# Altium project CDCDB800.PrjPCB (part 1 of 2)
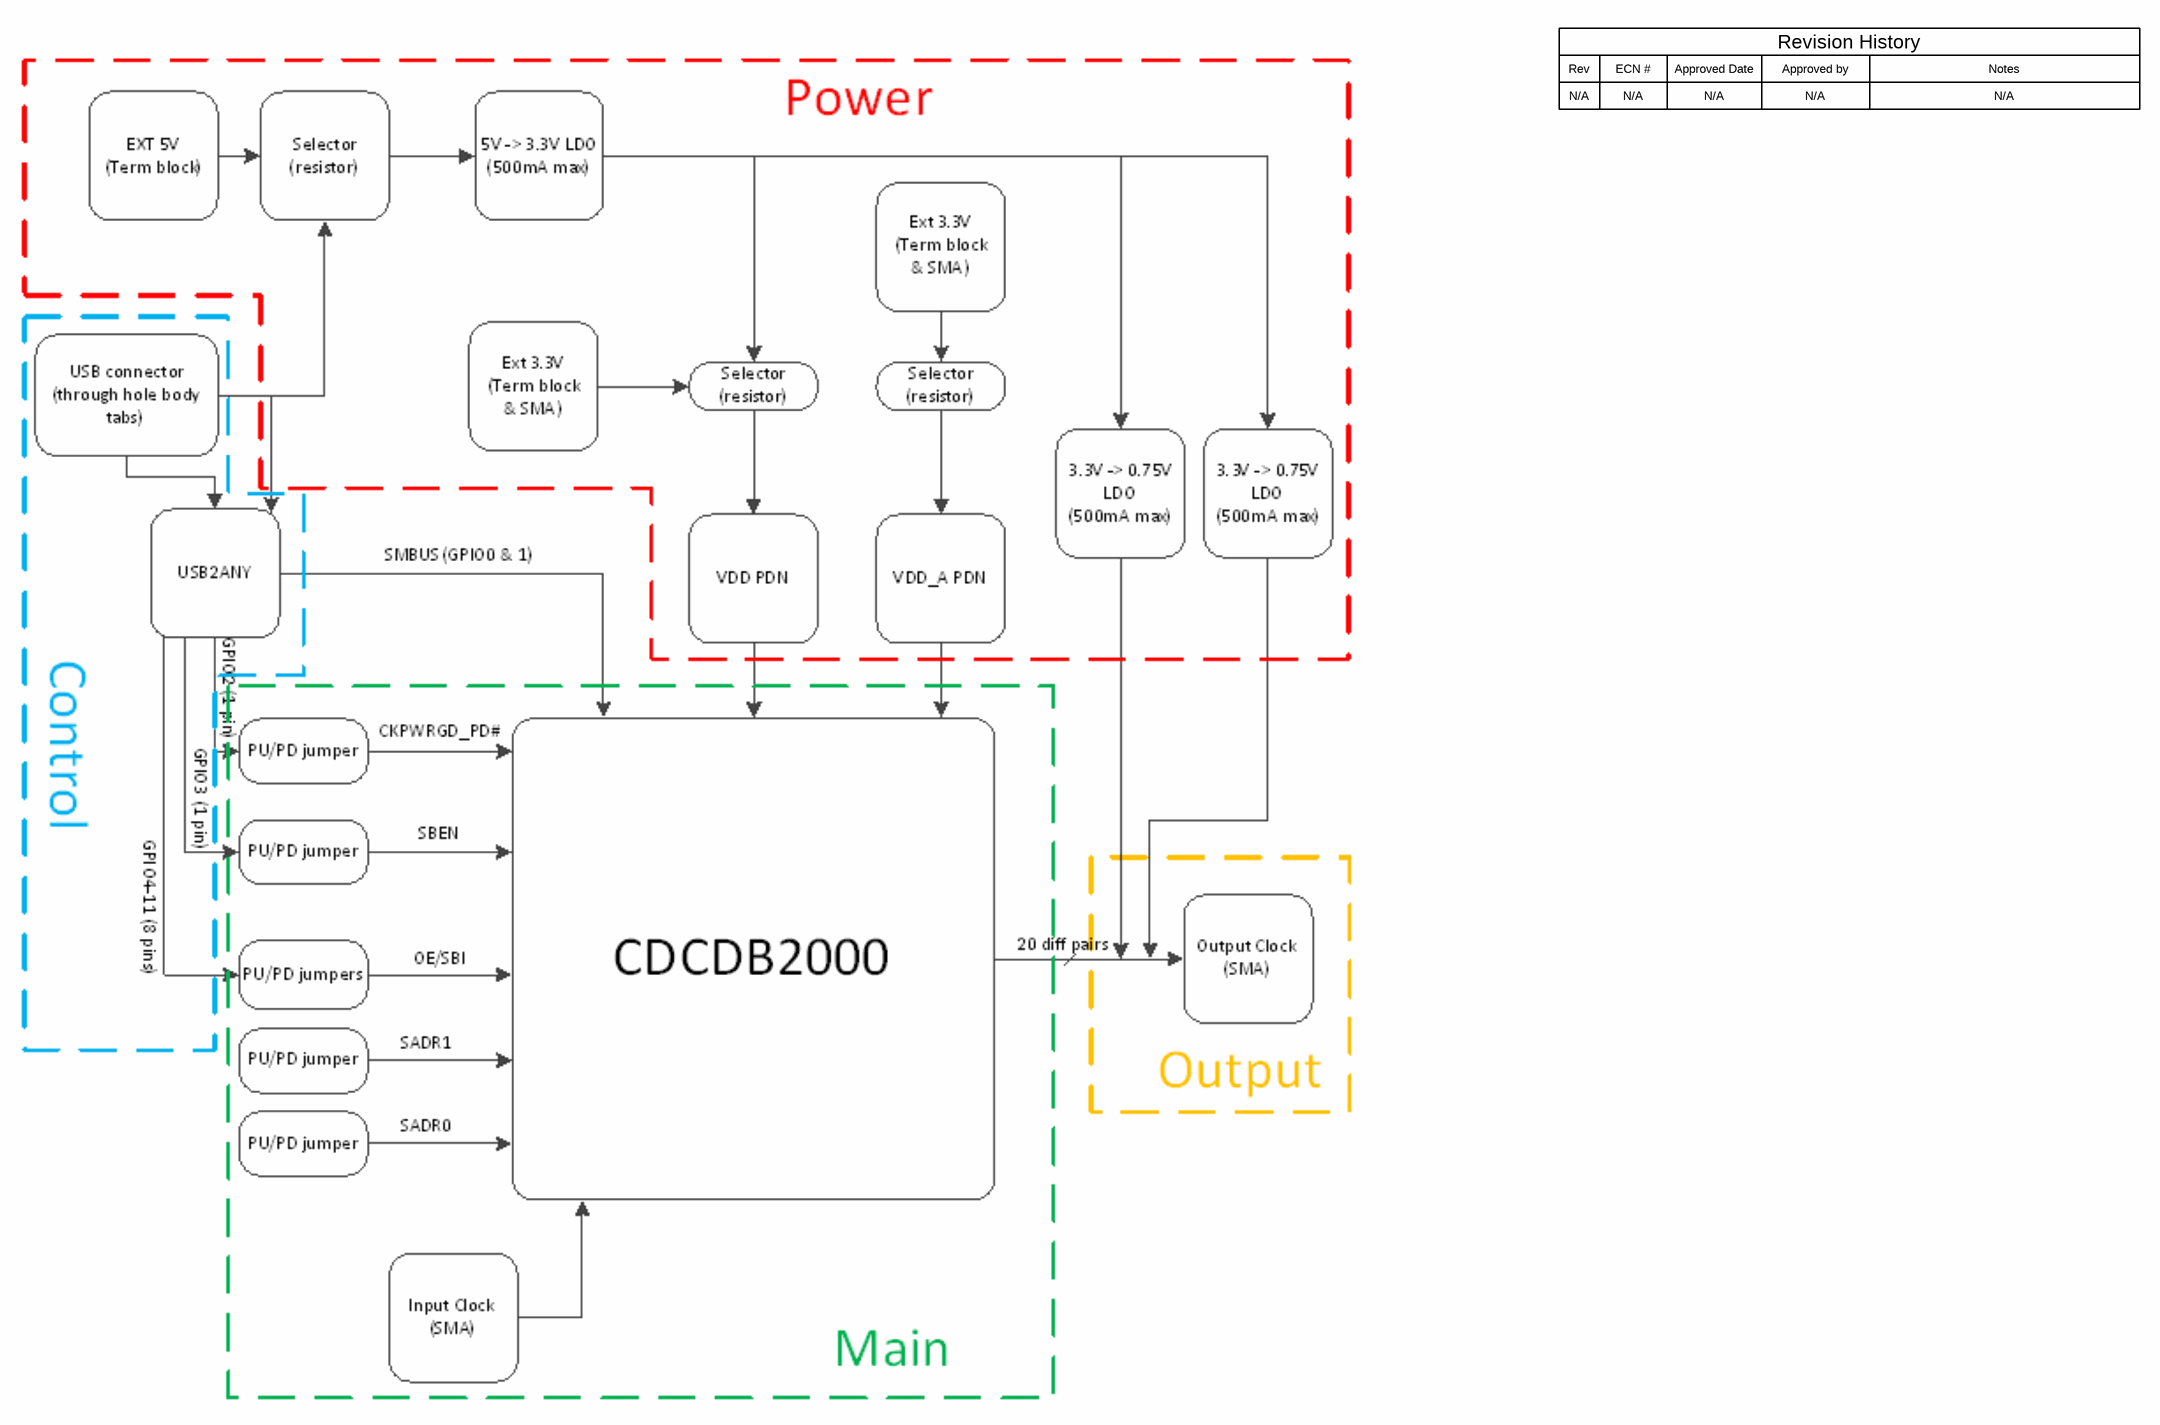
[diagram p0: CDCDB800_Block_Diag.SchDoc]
TID: N/A; TechSupport: http://www.ti.com/support; SCH_Rev: A; PRJ_Title: CDCDB800 EVM; PRJ_Number: CDCDB800; PRJ_Customer: Public Release; PCB_Rev: A; EVM_Orderable: CDCDB800 EVM; CopyrightYear: 2021
6 sheets, 245 parts. Net scope: flat (ports and power ports of the same name join across sheets).
Board file: CDCDB800.PcbDoc
Sheets:
  CDCDB800_Block_Diag.SchDoc
  CDCDB800_Control.SchDoc
  CDCDB800_Hardware.SchDoc
  CDCDB800_Main.SchDoc
  CDCDB800_Output.SchDoc
  CDCDB800_Power.SchDoc

## Sheet CDCDB800_Block_Diag.SchDoc: Block Diagram
size C; Date: Not shown in title block; ApprovedBy: Not shown in title block; CheckedBy: Not shown in title block; Author: Not shown in title block; CompanyName: Not shown in title block; DrawnBy: Robert Pulatie; Engineer: Not shown in title block; Organization: Not shown in title block; Address1: Not shown in title block; Address2: Not shown in title block; Address3: Not shown in title block; Address4: Not shown in title block; DocumentNumber: 1; Revision: Use project parameter SCH_Rev; SheetNumber: 1; SheetTotal: 6; PageSetup: Record=PageOptions¦CenterHorizontal=True¦CenterVertical=True¦PrintScale=1.00¦XCorrection=1.00¦YCorrection=1.00¦PrintKind=0¦BorderSize=5000000¦LeftOffset=0¦BottomOffset=0¦Orientation=2¦PaperLength=1000¦PaperWidth=1000¦Scale=100¦PaperSource=15¦PrintQuality=600¦MediaType=1¦DitherType=10¦PaperKind=Letter¦PrintScaleMode=1

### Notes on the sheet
- Rev
- N/A
- ECN #
- Approved Date
- Approved by
- Revision History
- Notes

## Sheet CDCDB800_Control.SchDoc: Control
size C; Date: Not shown in title block; ApprovedBy: Not shown in title block; CheckedBy: Not shown in title block; Author: Not shown in title block; CompanyName: Not shown in title block; DrawnBy: Robert Pulatie; Engineer: Not shown in title block; Organization: Not shown in title block; Address1: Not shown in title block; Address2: Not shown in title block; Address3: Not shown in title block; Address4: Not shown in title block; DocumentNumber: 5; Revision: Use project parameter SCH_Rev; SheetNumber: 5; SheetTotal: 6; PageSetup: Record=PageOptions¦CenterHorizontal=True¦CenterVertical=True¦PrintScale=1.00¦XCorrection=1.00¦YCorrection=1.00¦PrintKind=0¦BorderSize=5000000¦LeftOffset=0¦BottomOffset=0¦Orientation=2¦PaperLength=1000¦PaperWidth=1000¦Scale=100¦PaperSource=15¦PrintQuality=600¦MediaType=1¦DitherType=10¦PaperKind=Letter¦PrintScaleMode=1
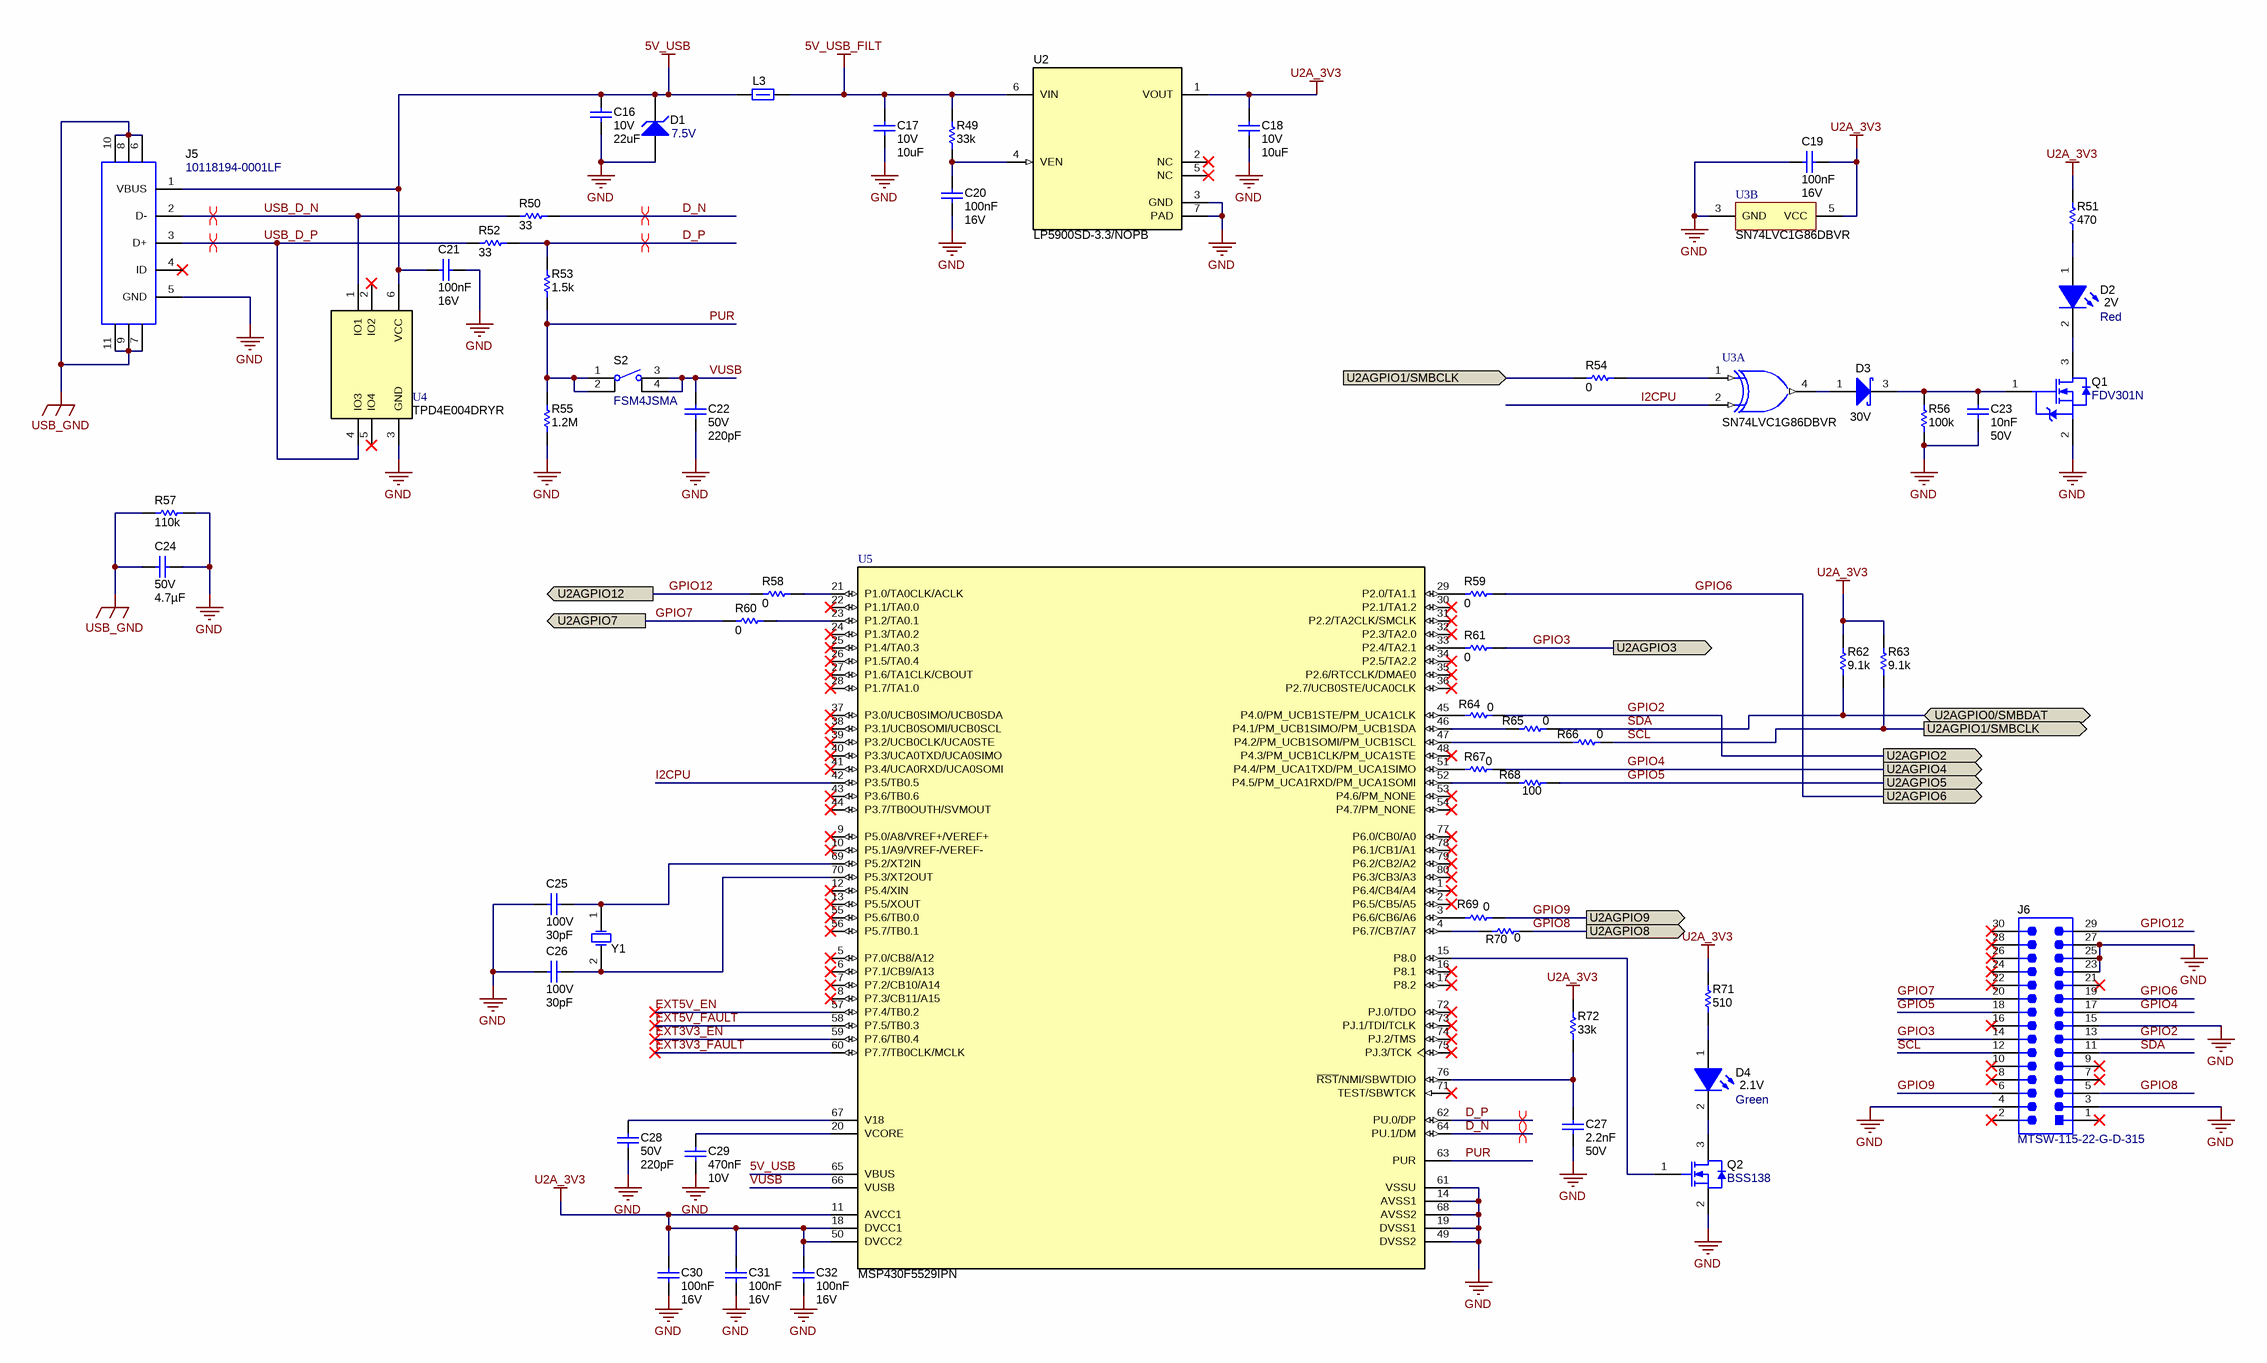
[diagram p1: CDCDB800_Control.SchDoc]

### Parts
C16  VDC_V: 10V  ValueDisplayed: 22uF  [0805_HV]  (hidden comment: LMK212BJ226MG-T)
C17  VDC_V: 10V  ValueDisplayed: 10uF  [0603]  (hidden comment: C1608X5R1A106M080AC)
C18  VDC_V: 10V  ValueDisplayed: 10uF  [0603]  (hidden comment: C1608X5R1A106M080AC)
C19  Cap_F: 100nF  VDC_V: 16V  [0603]  (hidden comment: C0603C104J4RACTU)
C20  Cap_F: 100nF  VDC_V: 16V  [0603]  (hidden comment: C0603C104J4RACTU)
C21  Cap_F: 100nF  VDC_V: 16V  [0603]  (hidden comment: C0603C104J4RACTU)
C22  VDC_V: 50V  ValueDisplayed: 220pF  [0603]  (hidden comment: 06035A221FAT2A)
C23  Cap_F: 10nF  VDC_V: 50V  [0603]  (hidden comment: C0603C103J5RACTU)
C24  VDC_V: 50V  ValueDisplayed: 4.7µF  [1206_190]  (hidden comment: C3216X7R1H475K160AE)
C25  VDC_V: 100V  ValueDisplayed: 30pF  [0603]  (hidden comment: GRM1885C2A300JA01D)
C26  VDC_V: 100V  ValueDisplayed: 30pF  [0603]  (hidden comment: GRM1885C2A300JA01D)
C27  Cap_F: 2.2nF  VDC_V: 50V  [0603]  (hidden comment: C0603C222K5RACTU)
C28  VDC_V: 50V  ValueDisplayed: 220pF  [0603]  (hidden comment: 06035A221FAT2A)
C29  Cap_F: 470nF  VDC_V: 10V  [0603]  (hidden comment: GRM188R71A474KA61D)
C30  Cap_F: 100nF  VDC_V: 16V  [0603]  (hidden comment: C0603C104J4RACTU)
C31  Cap_F: 100nF  VDC_V: 16V  [0603]  (hidden comment: C0603C104J4RACTU)
C32  Cap_F: 100nF  VDC_V: 16V  [0603]  (hidden comment: C0603C104J4RACTU)
D1  value 7.5V  [SMB]  (hidden comment: 1SMB5922BT3G)
D2  value Red  Value2: 2V  [LED_LTST-C170_Red]  (hidden comment: LTST-C170KRKT)
D3  value 30V  [SOT-23]  (hidden comment: BAT54-7-F)
D4  value Green  Value2: 2.1V  [LED_LTST-C190]  (hidden comment: LTST-C190GKT)
J5  10118194-0001LF  [FCI_10118194-0001LF]
J6  MTSW-115-22-G-D-315  [SAMTEC_MTSW-115-22-G-D-315]
L3  MPZ1608S600ATAH0  [0603]  (value not drawn)
Q1  FDV301N  [SOT-23]
Q2  BSS138  [SOT-23]
R49  ValueDisplayed: 33k  [0603]  (hidden comment: CRCW060333K0JNEA)
R50  ValueDisplayed: 33  [0402]  (hidden comment: CRCW040233R0JNED)
R51  ValueDisplayed: 470  [0603]  (hidden comment: CRCW0603470RJNEA)
R52  ValueDisplayed: 33  [0402]  (hidden comment: CRCW040233R0JNED)
R53  ValueDisplayed: 1.5k  [0402]  (hidden comment: CRCW04021K50JNED)
R54  ValueDisplayed: 0  [0603]  (hidden comment: CRCW06030000Z0EA)
R55  ValueDisplayed: 1.2M  [0603]  (hidden comment: CRCW06031M20JNEA)
R56  ValueDisplayed: 100k  [0603]  (hidden comment: CRCW0603100KJNEA)
R57  ValueDisplayed: 110k  [1206]  (hidden comment: RC1206FR-07110KL)
R58  ValueDisplayed: 0  [0603]  (hidden comment: CRCW06030000Z0EA)
R59  ValueDisplayed: 0  [0603]  (hidden comment: CRCW06030000Z0EA)
R60  ValueDisplayed: 0  [0603]  (hidden comment: CRCW06030000Z0EA)
R61  ValueDisplayed: 0  [0603]  (hidden comment: CRCW06030000Z0EA)
R62  ValueDisplayed: 9.1k  [0603]  (hidden comment: RC0603JR-079K1L)
R63  ValueDisplayed: 9.1k  [0603]  (hidden comment: RC0603JR-079K1L)
R64  ValueDisplayed: 0  [0603]  (hidden comment: CRCW06030000Z0EA)
R65  ValueDisplayed: 0  [0603]  (hidden comment: CRCW06030000Z0EA)
R66  ValueDisplayed: 0  [0603]  (hidden comment: CRCW06030000Z0EA)
R67  ValueDisplayed: 0  [0603]  (hidden comment: CRCW06030000Z0EA)
R68  ValueDisplayed: 100  [0603]  (hidden comment: CRCW0603100RJNEA)
R69  ValueDisplayed: 0  [0603]  (hidden comment: CRCW06030000Z0EA)
R70  ValueDisplayed: 0  [0603]  (hidden comment: CRCW06030000Z0EA)
R71  ValueDisplayed: 510  [0603]  (hidden comment: CRCW0603510RJNEA)
R72  ValueDisplayed: 33k  [0603]  (hidden comment: CRCW060333K0JNEA)
S2  FSM4JSMA  [SW_FSM4JSMA]
U2  LP5900SD-3.3/NOPB  [NGF0006A]
U3  SN74LVC1G86DBVR  [DBV0005A_N]  (parts A,B of 2)
U4  TPD4E004DRYR  [DRY0006A]
U5  MSP430F5529IPN  [PN0080A_N]
Y1  ECS-240-20-5PX-TR  [XTAL_CSM-7X]  (value not drawn)

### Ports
U2AGPIO0/SMBDAT (bidir), U2AGPIO1/SMBCLK (in), U2AGPIO1/SMBCLK (out), U2AGPIO2 (out), U2AGPIO3 (out), U2AGPIO4 (out), U2AGPIO5 (out), U2AGPIO6 (out), U2AGPIO7 (out), U2AGPIO8 (out), U2AGPIO9 (out), U2AGPIO12 (out)

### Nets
5V_USB: C16.1 C21.2 D1.1(K) J5.1(VBUS) L3.1 U4.6(VCC) U5.65(VBUS)
5V_USB_FILT: C17.1 L3.2 R49.2 U2.6(VIN)
GND: C16.2 C17.2 C18.2 C19.2 C20.2 C21.1 C22.2 C23.2 C24.1 C25.2 C26.2 C27.2 C28.2 C29.2 C30.2 C31.2 C32.2 D1.2(A) J5.5(GND) J6.3 J6.4 J6.15 J6.23 J6.25 J6.27 Q1.2(S) Q2.2(S) R55.1 R56.1 R57.2 U2.3(GND) U2.7(PAD) U3.3(GND) U4.3(GND) U5.14(AVSS1) U5.19(DVSS1) U5.49(DVSS2) U5.61(VSSU) U5.68(AVSS2)
U2A_3V3: C18.1 C19.1 C30.1 C31.1 C32.1 R51.2 R62.2 R63.2 R71.2 R72.2 U2.1(VOUT) U3.5(VCC) U5.11(AVCC1) U5.18(DVCC1) U5.50(DVCC2)
USB_GND: C24.2 J5.6 J5.7 J5.8 J5.9 J5.10 J5.11 R57.1
D_N: R50.2 U5.64(PU.1/DM)
D_P: R52.2 R53.2 U5.62(PU.0/DP)
EXT3V3_EN: U5.59(P7.6/TB0.4)
EXT3V3_FAULT: U5.60(P7.7/TB0CLK/MCLK)
EXT5V_EN: U5.57(P7.4/TB0.2)
EXT5V_FAULT: U5.58(P7.5/TB0.3)
GPIO2: J6.13 R64.2 ; port U2AGPIO2
GPIO3: J6.14 R61.2 ; port U2AGPIO3
GPIO4: J6.17 R67.2 ; port U2AGPIO4
GPIO5: J6.18 R68.2 ; port U2AGPIO5
GPIO6: J6.19 R59.2 ; port U2AGPIO6
GPIO7: J6.20 R60.1 ; port U2AGPIO7
GPIO8: J6.5 R70.2 ; port U2AGPIO8
GPIO9: J6.6 R69.2 ; port U2AGPIO9
GPIO12: J6.29 R58.1 ; port U2AGPIO12
I2CPU: U3.2(B) U5.42(P3.5/TB0.5)
PUR: R53.1 R55.2 S2.1 S2.2 U5.63(PUR)
SCL: J6.12 R54.1 R63.1 R66.2 ; port U2AGPIO1/SMBCLK
SDA: J6.11 R62.1 R65.2 ; port U2AGPIO0/SMBDAT
USB_D_N: J5.2(D-) R50.1 U4.1(IO1)
USB_D_P: J5.3(D+) R52.1 U4.4(IO3)
VUSB: C22.1 S2.3 S2.4 U5.66(VUSB)
NetC20_1: C20.1 R49.1 U2.4(VEN)
NetC23_1: C23.1 D3.3(K) Q1.1(G) R56.2
NetC25_1: C25.1 U5.69(P5.2/XT2IN) Y1.1(OSC1)
NetC26_1: C26.1 U5.70(P5.3/XT2OUT) Y1.2(OSC2)
NetC27_1: C27.1 R72.1 U5.76(~{RST}/NMI/SBWTDIO)
NetC28_1: C28.1 U5.67(V18)
NetC29_1: C29.1 U5.20(VCORE)
NetD2_1: D2.1(A) R51.1
NetD2_2: D2.2(K) Q1.3(D)
NetD3_1: D3.1(A) U3.4(Y)
NetD4_1: D4.1(A) R71.1
NetD4_2: D4.2(K) Q2.3(D)
NetQ2_1: Q2.1(G) U5.15(P8.0)
NetR54_2: R54.2 U3.1(A)
NetR58_2: R58.2 U5.21(P1.0/TA0CLK/ACLK)
NetR59_1: R59.1 U5.29(P2.0/TA1.1)
NetR60_2: R60.2 U5.23(P1.2/TA0.1)
NetR61_1: R61.1 U5.33(P2.4/TA2.1)
NetR64_1: R64.1 U5.45(P4.0/PM_UCB1STE/PM_UCA1CLK)
NetR65_1: R65.1 U5.46(P4.1/PM_UCB1SIMO/PM_UCB1SDA)
NetR66_1: R66.1 U5.47(P4.2/PM_UCB1SOMI/PM_UCB1SCL)
NetR67_1: R67.1 U5.51(P4.4/PM_UCA1TXD/PM_UCA1SIMO)
NetR68_1: R68.1 U5.52(P4.5/PM_UCA1RXD/PM_UCA1SOMI)
NetR69_1: R69.1 U5.3(P6.6/CB6/A6)
NetR70_1: R70.1 U5.4(P6.7/CB7/A7)

Not connected (* = marked no-connect by the designer): J5 4(ID)*; J6 1* 2* 7* 8* 9* 10* 16* 21* 22* 24* 26* 28* 30*; U2 2(NC)* 5(NC)*; U4 2(IO2)* 5(IO4)*; U5 1(P6.4/CB4/A4)* 2(P6.5/CB5/A5)* 5(P7.0/CB8/A12)* 6(P7.1/CB9/A13)* 7(P7.2/CB10/A14)* 8(P7.3/CB11/A15)* 9(P5.0/A8/VREF+/VEREF+)* 10(P5.1/A9/VREF-/VEREF-)* 12(P5.4/XIN)* 13(P5.5/XOUT)* 16(P8.1)* 17(P8.2)* 22(P1.1/TA0.0)* 24(P1.3/TA0.2)* 25(P1.4/TA0.3)* 26(P1.5/TA0.4)* 27(P1.6/TA1CLK/CBOUT)* 28(P1.7/TA1.0)* 30(P2.1/TA1.2)* 31(P2.2/TA2CLK/SMCLK)* 32(P2.3/TA2.0)* 34(P2.5/TA2.2)* 35(P2.6/RTCCLK/DMAE0)* 36(P2.7/UCB0STE/UCA0CLK)* 37(P3.0/UCB0SIMO/UCB0SDA)* 38(P3.1/UCB0SOMI/UCB0SCL)* 39(P3.2/UCB0CLK/UCA0STE)* 40(P3.3/UCA0TXD/UCA0SIMO)* 41(P3.4/UCA0RXD/UCA0SOMI)* 43(P3.6/TB0.6)* 44(P3.7/TB0OUTH/SVMOUT)* 48(P4.3/PM_UCB1CLK/PM_UCA1STE)* 53(P4.6/PM_NONE)* 54(P4.7/PM_NONE)* 55(P5.6/TB0.0)* 56(P5.7/TB0.1)* 71(TEST/SBWTCK)* 72(PJ.0/TDO)* 73(PJ.1/TDI/TCLK)* 74(PJ.2/TMS)* 75(PJ.3/TCK)* 77(P6.0/CB0/A0)* 78(P6.1/CB1/A1)* 79(P6.2/CB2/A2)* 80(P6.3/CB3/A3)*

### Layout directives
differential pair: D_N, D_P, USB_D_N, USB_D_P

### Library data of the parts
C16 = CMP-0008403-2: CAP, CERM, 22 uF, 10 V, +/- 20%, X5R, 0805; Manufacturer: Taiyo Yuden; TaMin_C: -55°C; Polarized: N; SizeAreaWB_mm2: 6.75; Value1: Unknown; U/M: EA; Value: 22uF; TaMax_C: 85°C; SizeZ_mm: 1.45; SizeX_mm: 2; SizeY_mm: 1.25; Cap_Case: 0805; SizeArea_mm2: 2.5; Cap_F: 22µF; AEC Category: Q200
C17 C18 = CMP-0007003-5: CAP, CERM, 10 uF, 10 V, +/- 20%, X5R, 0603; Manufacturer: TDK; TaMin_C: -55°C; ESR_ohm: 7.8m; Polarized: N; SizeAreaWB_mm2: 4.68; Value1: 0.0078 ohm; U/M: EA; Value: 10uF; TaMax_C: 85°C; SizeZ_mm: 1; SizeX_mm: 1.6; SizeY_mm: 0.8; SizeArea_mm2: 1.28; Cap_F: 10µF; IRMS_A: 1.85A; AEC Category: Q200
C19-C21 C30-C32 = CMP-0006857-4: CAP, CERM, 0.1 uF, 16 V, +/- 5%, X7R, 0603; Manufacturer: Kemet; TaMin_C: -55°C; Polarized: N; SizeAreaWB_mm2: 4.68; Value1: Unknown; U/M: EA; Value: 0.1uF; TaMax_C: 125°C; SizeZ_mm: 1; SizeX_mm: 1.6; SizeY_mm: 0.8; SizeArea_mm2: 1.28; AEC Category: Q200
C22 C28 = CMP-0006776-4: CAP, CERM, 220 pF, 50 V, +/- 1%, C0G/NP0, 0603; Manufacturer: AVX; TaMin_C: -55°C; ESR_ohm: 0.083; Polarized: N; SizeAreaWB_mm2: 4.68; Value1: 0.083 ohm; U/M: EA; Value: 220pF; TaMax_C: 125°C; SizeZ_mm: 1; SizeX_mm: 1.6; SizeY_mm: 0.8; SizeArea_mm2: 1.28; AEC Category: Q200
C23 = CMP-0006850-4: CAP, CERM, 0.01 uF, 50 V, +/- 5%, X7R, 0603; Manufacturer: Kemet; TaMin_C: -55°C; Polarized: N; SizeAreaWB_mm2: 4.68; Value1: Unknown; U/M: EA; Value: 0.01uF; TaMax_C: 125°C; SizeZ_mm: 1; SizeX_mm: 1.6; SizeY_mm: 0.8; SizeArea_mm2: 1.28; AEC Category: Q200
C24 = CMP-0082522-1: CAP, CERM, 4.7 µF, 50 V,+/- 10%, X7R, 1206; Manufacturer: TDK; SizeAreaWB_mm2: 10.92; SizeArea_mm2: 5.12; AEC Qualified: N; AEC Category: Q200; Value: 4.7uF; TaMax_C: 125°C; SizeZ_mm: 1.9; TaMin_C: -55°C; SizeY_mm: 1.6; U/M: EA; SizeX_mm: 3.2; Cap_Case: 1206
C25 C26 = CMP-0007261-4: CAP, CERM, 30 pF, 100 V, +/- 5%, C0G/NP0, 0603; Manufacturer: MuRata; TaMin_C: -55°C; Polarized: N; SizeAreaWB_mm2: 4.68; Value1: Unknown; U/M: EA; Value: 30pF; TaMax_C: 125°C; SizeZ_mm: 1; SizeX_mm: 1.6; SizeY_mm: 0.8; SizeArea_mm2: 1.28; AEC Category: Q200
C27 = CMP-0006898-4: CAP, CERM, 2200 pF, 50 V, +/- 10%, X7R, 0603; Manufacturer: Kemet; TaMin_C: -55°C; Polarized: N; SizeAreaWB_mm2: 4.68; Value1: Unknown; U/M: EA; Value: 2200pF; TaMax_C: 125°C; SizeZ_mm: 1; SizeX_mm: 1.6; SizeY_mm: 0.8; SizeArea_mm2: 1.28; AEC Category: Q200
C29 = CMP-0007373-4: CAP, CERM, 0.47 uF, 10 V, +/- 10%, X7R, 0603; Manufacturer: MuRata; TaMin_C: -55°C; Polarized: N; SizeAreaWB_mm2: 4.68; Value1: Unknown; U/M: EA; Value: 0.47uF; TaMax_C: 125°C; SizeZ_mm: 1; SizeX_mm: 1.6; SizeY_mm: 0.8; SizeArea_mm2: 1.28; AEC Category: Q200
D1 = CMP-0005670-3: Diode, Zener, 7.5 V, 550 mW, SMB; Manufacturer: ON Semiconductor; SizeArea_mm2: 21.336; SizeY_mm: 3.81; Value1: 0.55W; Power_W: 550mW; SizeZ_mm: 2.6; AEC Category: Q101; RJA_CperW: 226; SizeX_mm: 5.6; SizeAreaWB_mm2: 44.156
D2 = CMP-0002829-3: LED, Red, SMD; Manufacturer: Lite-On; SizeZ_mm: 1.2; Value1: W; SizeY_mm: 1.25; SizeArea_mm2: 2.5; SizeX_mm: 2; SizeAreaWB_mm2: 6.75; Io_A: 20mA; Type: AlInGaP
D3 = CMP-0028451-2: Diode, Schottky, 30 V, 0.2 A, SOT-23; Manufacturer: Diodes Inc.; SizeAreaWB_mm2: 14; SizeZ_mm: 1.1; Green_Lifecycle: Active; SizeY_mm: 3; Io_A: 200mA; SizeArea_mm2: 7.5; Green_REACh: Passed; Value1: 0.2A; Value2: 0.65V; TJmax_C: 125°C; Vf_V: 650mV; AEC Category: Q101; SizeX_mm: 2.5
D4 = CMP-0002827-3: LED, Green, SMD; Manufacturer: Lite-On; Power_TotalModule: 100mW; Io_A: 20mA; Value1: 0.1W
J5 = CMP-0074596-2: Receptacle, USB 2.0, Micro-USB Type B, R/A, SMT; Manufacturer: FCI; CNHeader: False; Current_A: 1.8A; Gender: Female; Voltage_V: 100V; Row_Count: 1; Pitch_mm: 0.65; ContactFinish: Gold; CT: True; Cert_UL: Y
J6 = CMP-0075468-1: Header, 100mil, 15x2, Gold, TH; Manufacturer: Samtec; Green_Lifecycle: Active; Green_REACh: Passed; CT: False; CNHeader: True
L3 = CMP-0003426-2: Ferrite Bead, 60 ohm @ 100 MHz, 3.5 A, 0603; Manufacturer: TDK; ZTyp@100MHz_Ohm: 60; SizeAreaWB_mm2: 4.68; DCR_ohm: 0.02; Value1: 0.02 ohm; Value: 60 ohm; Imax_A: 3.5A; SizeZ_mm: 1; SizeX_mm: 1.6; SizeY_mm: 0.8; SizeArea_mm2: 1.28
Q1 = CMP-0000281-1: MOSFET, N-CH, 25 V, 0.22 A, SOT-23; Alternate Manufacturer: None; Manufacturer: Fairchild Semiconductor; SizeZ_mm: 1.1; ChType: N; Value2: 0.49 nC; VdsMax_V: 25V; SizeX_mm: 2.5; SizeY_mm: 3; Vgs_V: 8V; Value: 25V; Rdson45_ohm: 4; SizeArea_mm2: 7.5; AEC Category: Q101; IdsMax_A: 220mA; SizeAreaWB_mm2: 14; U/M: EA; QgTyp_nC: 0.49
Q2 = CMP-0000755-1: MOSFET, N-CH, 50 V, 0.22 A, SOT-23; Alternate Manufacturer: None; Manufacturer: Fairchild Semiconductor; SizeZ_mm: 1.1; ChType: N; Value2: 1.7 nC; VdsMax_V: 50V; SizeX_mm: 2.5; SizeY_mm: 3; Vgs_V: 20V; Value: 50V; Rdson45_ohm: 6; SizeArea_mm2: 7.5; AEC Category: Q101; IdsMax_A: 220mA; SizeAreaWB_mm2: 14; U/M: EA; QgTyp_nC: 1.7
R49 R72 = CMP-0025786-4: RES, 33 k, 5%, 0.1 W, AEC-Q200 Grade 0, 0603; Manufacturer: Vishay-Dale; Power_W: 100mW; TempCo: 200 ppm/C; Value_Code: 33k0; Value: 33k; EIA_Code: E24; SizeX_mm: 1.6; SizeY_mm: 0.8; SizeZ_mm: 1; Value2: 0.1W; SizeArea_mm2: 1.28; AEC Qualified: Y; VDC_V: 75V; AEC Category: Q200; AEC Grade: 0
R50 R52 = CMP-0026908-3: RES, 33, 5%, 0.063 W, AEC-Q200 Grade 0, 0402; Manufacturer: Vishay-Dale; Power_W: 63mW; TempCo: 200 ppm/C; Value_Code: 33R0; Value: 33; EIA_Code: E24; SizeX_mm: 1; SizeY_mm: 0.5; SizeZ_mm: 0.6; Value2: 0.063W; AEC Qualified: Y; VDC_V: 50V; AEC Category: Q200; AEC Grade: 0
R51 = CMP-0025813-4: RES, 470, 5%, 0.1 W, AEC-Q200 Grade 0, 0603; Manufacturer: Vishay-Dale; Power_W: 100mW; TempCo: 200 ppm/C; Value_Code: 470R; Value: 470; EIA_Code: E24; SizeX_mm: 1.6; SizeY_mm: 0.8; SizeZ_mm: 1; Value2: 0.1W; SizeArea_mm2: 1.28; AEC Qualified: Y; VDC_V: 75V; AEC Category: Q200; AEC Grade: 0
R53 = CMP-0026856-5: RES, 1.5 k, 5%, 0.063 W, AEC-Q200 Grade 0, 0402; Manufacturer: Vishay-Dale; Power_W: 63mW; TempCo: 200 ppm/C; Value_Code: 1k50; Value: 1.5k; EIA_Code: E24; SizeX_mm: 1; SizeY_mm: 0.5; SizeZ_mm: 0.6; Value2: 0.063W; AEC Qualified: Y; VDC_V: 50V; AEC Category: Q200; AEC Grade: 0
R54 R58-R61 R64-R67 R69 R70 = CMP-0025697-4: RES, 0, 5%, 0.1 W, AEC-Q200 Grade 0, 0603; Manufacturer: Vishay-Dale; Power_W: 100mW; TempCo: 200 ppm/C; Value_Code: 0000; Value: 0; EIA_Code: E24; SizeX_mm: 1.6; SizeY_mm: 0.8; SizeZ_mm: 1; Value2: 0.1W; SizeArea_mm2: 1.28; AEC Qualified: Y; VDC_V: 75V; AEC Category: Q200
R55 = CMP-0025738-4: RES, 1.2 M, 5%, 0.1 W, AEC-Q200 Grade 0, 0603; Manufacturer: Vishay-Dale; Power_W: 100mW; TempCo: 200 ppm/C; Value_Code: 1M20; Value: 1.2Meg; EIA_Code: E24; SizeX_mm: 1.6; SizeY_mm: 0.8; SizeZ_mm: 1; Value2: 0.1W; SizeArea_mm2: 1.28; AEC Qualified: Y; VDC_V: 75V; AEC Category: Q200; AEC Grade: 0
R56 = CMP-0025698-4: RES, 100 k, 5%, 0.1 W, AEC-Q200 Grade 0, 0603; Manufacturer: Vishay-Dale; Power_W: 100mW; TempCo: 200 ppm/C; Value: 100k; EIA_Code: E24; SizeX_mm: 1.6; SizeY_mm: 0.8; SizeZ_mm: 1; Value2: 0.1W; SizeArea_mm2: 1.28; AEC Qualified: Y; VDC_V: 75V; AEC Category: Q200; AEC Grade: 0
R57 = CMP-0017852-2: RES, 110 k, 1%, 0.25 W, 1206; Manufacturer: Yageo America; Power_W: 250mW; TempCo: 100 ppm/C; U/M: EA; Value: 110k; EIA_Code: E96; SizeX_mm: 3.2; SizeY_mm: 1.6; SizeZ_mm: 1.35; Value2: 0.25W; SizeArea_mm2: 5.12; VDC_V: 200V; AEC Category: Q200
R62 R63 = CMP-0025944-5: RES, 9.1 k, 5%, 0.1 W, 0603; Manufacturer: Yageo; Power_W: 100mW; TempCo: 100 ppm/C; Value_Code: 9k10; Value: 9.1k; EIA_Code: E24; SizeX_mm: 1.6; SizeY_mm: 0.8; SizeZ_mm: 1; Value2: 0.1W; SizeArea_mm2: 1.28; AEC Qualified: N; VDC_V: 75V; AEC Category: Q200; SizeAreaWB_mm2: 4.68
R68 = CMP-0025700-4: RES, 100, 5%, 0.1 W, AEC-Q200 Grade 0, 0603; Manufacturer: Vishay-Dale; Power_W: 100mW; TempCo: 200 ppm/C; Value_Code: 100R; Value: 100; EIA_Code: E24; SizeX_mm: 1.6; SizeY_mm: 0.8; SizeZ_mm: 1; Value2: 0.1W; SizeArea_mm2: 1.28; AEC Qualified: Y; VDC_V: 75V; AEC Category: Q200; AEC Grade: 0
R71 = CMP-0025823-4: RES, 510, 5%, 0.1 W, AEC-Q200 Grade 0, 0603; Manufacturer: Vishay-Dale; Power_W: 100mW; TempCo: 200 ppm/C; Value_Code: 510R; Value: 510; EIA_Code: E24; SizeX_mm: 1.6; SizeY_mm: 0.8; SizeZ_mm: 1; Value2: 0.1W; SizeArea_mm2: 1.28; AEC Qualified: Y; VDC_V: 75V; AEC Category: Q200; AEC Grade: 0
S2 = CMP-0002134-3: Switch, Tactile, SPST-NO, 0.05A, 12V, SMT; Manufacturer: TE Connectivity; CurrentRating_mA: 50A; PositionCount: 1; SwitchFunction: Off-Mom
U2 = CMP-0066010-1: 150-mA Ultra-Low Noise LDO for RF and Analog Circuits Requires No Bypass Capacitor, NGF0006A (WSON-6); Alternate Manufacturer: Texas Instruments; Green_Lifecycle: Active; SizeAreaWB_mm2: 11.2; Green_REACh: Passed; U/M: EA; SizeZ_mm: 0.8; SizeX_mm: 2.5; SizeY_mm: 2.2; SizeArea_mm2: 5.5; CompType: IC
U3 = CMP-0052046-2: Single 2-Input Exclusive-OR Gate, DBV0005A (SOT-23-5); Manufacturer: Texas Instruments; Schmitt Trigger: No; Output Type: CMOS; Bits(#): 1; Rating: Catalog; VCC(Max)(V): 5.5; Input Type: CMOS/TTL; F @ Nom Voltage(Max)(Mhz): 150; Voltage(Nom)(V): 1.8,2.5,3.3,5; VCC(Min)(V): 1.65; Output Drive (IOL/IOH)(Max)(mA): 32/-32; ICC @ Nom Voltage(Max)(mA): 0.01; Logic: True; Gate Type: XOR; tpd @ Nom Voltage(Max)(ns): 9.9,5.5,5,4; AEC Category: Q200; AEC Qualified: N; CompType: IC; SizeAreaWB_mm2: 14.82; SizeArea_mm2: 8.12; SizeX_mm: 2.8; SizeY_mm: 2.9; SizeZ_mm: 1.45
U4 = CMP-0043115-3: 4-Channel ESD Protection Array for High-Speed Data Interfaces, DRY0006A (USON-6); Manufacturer: Texas Instruments; IO Leakage Current(nA): 1; USB High Speed: TRUE; IO Capacitance(Typ)(pF): 1.6; Eco-Plan: Green (RoHS & no Sb/Br); IEC 61000-4-2 Contact(+/- kV): 8; Breakdown Voltage(Min)(V): 6; IEC 61000-4-2 Air-Gap(+/- kV): 12; AEC Category: Q200; AEC Qualified: N; CompType: IC; SizeAreaWB_mm2: 4.9; SizeArea_mm2: 1.45; SizeX_mm: 1.0; SizeZ_mm: 0.6; Rating: Catalog
U5 = CMP-0038965-1: 25 MHz Mixed Signal Microcontroller with 128 KB Flash, 8192 B SRAM and 63 GPIOs, -40 to 85 degC, 80-pin QFP (PN), Green (RoHS & no Sb/Br); Manufacturer: Texas Instruments; Real-Time Clock: Yes; Multiplier: 32x32; Frequency(MHz): 25; USCI_A (UART/LIN/IrDA/SPI): 2; SubFamily: 5 Series; Timers - 16-bit: 4; ADC Channels: 16; GPIO: 63; SRAM(B): 8192; DMA: 3; ADC: 12-bit SAR; Flash(KB): 128; USB: 1
Y1 = CMP-0004572-3: Crystal, 24.000 MHz, 20pF, SMD; Manufacturer: ECS Inc.; TaMin_C: -10°C; Frequency Stability: +/-50ppm; Frequency_Fixed: 24MHz; TaMax_C: 70°C

## Sheet CDCDB800_Hardware.SchDoc: Hardware
size C; Date: Not shown in title block; ApprovedBy: Not shown in title block; CheckedBy: Not shown in title block; Author: Not shown in title block; CompanyName: Not shown in title block; DrawnBy: Robert Pulatie; Engineer: Not shown in title block; Organization: Not shown in title block; Address1: Not shown in title block; Address2: Not shown in title block; Address3: Not shown in title block; Address4: Not shown in title block; DocumentNumber: 6; Revision: Use project parameter SCH_Rev; SheetNumber: 6; SheetTotal: 6; PageSetup: Record=PageOptions¦CenterHorizontal=True¦CenterVertical=True¦PrintScale=1.00¦XCorrection=1.00¦YCorrection=1.00¦PrintKind=0¦BorderSize=5000000¦LeftOffset=0¦BottomOffset=0¦Orientation=2¦PaperLength=1000¦PaperWidth=1000¦Scale=100¦PaperSource=15¦PrintQuality=600¦MediaType=1¦DitherType=10¦PaperKind=Letter¦PrintScaleMode=1
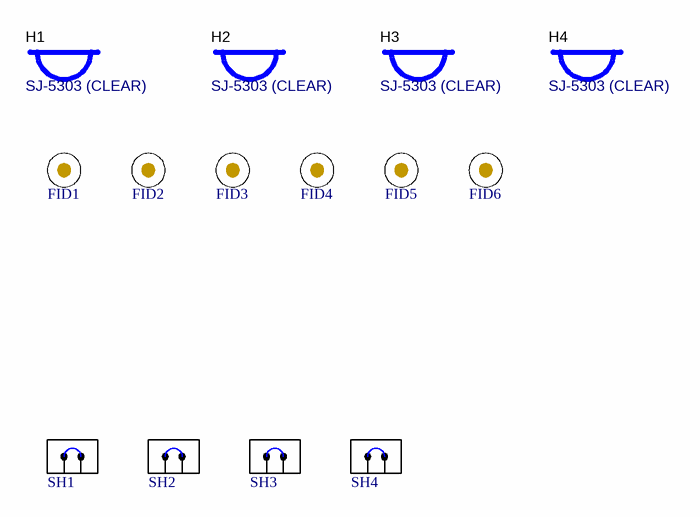
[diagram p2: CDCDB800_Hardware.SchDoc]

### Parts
FID1  Fiducial  [Fiducial10-20]  (value not drawn)
FID2  Fiducial  [Fiducial10-20]  (value not drawn)
FID3  Fiducial  [Fiducial10-20]  (value not drawn)
FID4  Fiducial  [Fiducial10-20]  (value not drawn)
FID5  Fiducial  [Fiducial10-20]  (value not drawn)
FID6  Fiducial  [Fiducial10-20]  (value not drawn)
H1  SJ-5303 (CLEAR)  [Bumpon_SJ5003Transparent]
H2  SJ-5303 (CLEAR)  [Bumpon_SJ5003Transparent]
H3  SJ-5303 (CLEAR)  [Bumpon_SJ5003Transparent]
H4  SJ-5303 (CLEAR)  [Bumpon_SJ5003Transparent]
SH1  SNT-100-BK-G  [SNT-100-BK-G]  (value not drawn)
SH2  SNT-100-BK-G  [SNT-100-BK-G]  (value not drawn)
SH3  SNT-100-BK-G  [SNT-100-BK-G]  (value not drawn)
SH4  SNT-100-BK-G  [SNT-100-BK-G]  (value not drawn)

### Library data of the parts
FID1-FID6 = CMP-0077181-1: Fiducial mark.  There is nothing to buy or mount.
H1-H4 = CMP-0003620-1: Bumpon, Hemisphere, 0.44 X 0.20, Clear; Manufacturer: 3M
SH1-SH4 = CMP-0003623-3: Shunt, 100mil, Gold plated, Black; Alternate PartNumber: 969102-0000-DA; Manufacturer: Samtec; Alternate Manufacturer: 3M; Value: 1x2; Note: You can "mate" this to a header by matching the designator.  i.e. use SH-J3 for header J3

## Sheet CDCDB800_Main.SchDoc: Main
size C; Date: Not shown in title block; ApprovedBy: Not shown in title block; CheckedBy: Not shown in title block; Author: Not shown in title block; CompanyName: Not shown in title block; DrawnBy: Robert Pulatie; Engineer: Not shown in title block; Organization: Not shown in title block; Address1: Not shown in title block; Address2: Not shown in title block; Address3: Not shown in title block; Address4: Not shown in title block; DocumentNumber: 3; Revision: Use project parameter SCH_Rev; SheetNumber: 3; SheetTotal: 6; PageSetup: Record=PageOptions¦CenterHorizontal=True¦CenterVertical=True¦PrintScale=1.00¦XCorrection=1.00¦YCorrection=1.00¦PrintKind=0¦BorderSize=5000000¦LeftOffset=0¦BottomOffset=0¦Orientation=2¦PaperLength=1000¦PaperWidth=1000¦Scale=100¦PaperSource=15¦PrintQuality=600¦MediaType=1¦DitherType=10¦PaperKind=Letter¦PrintScaleMode=1
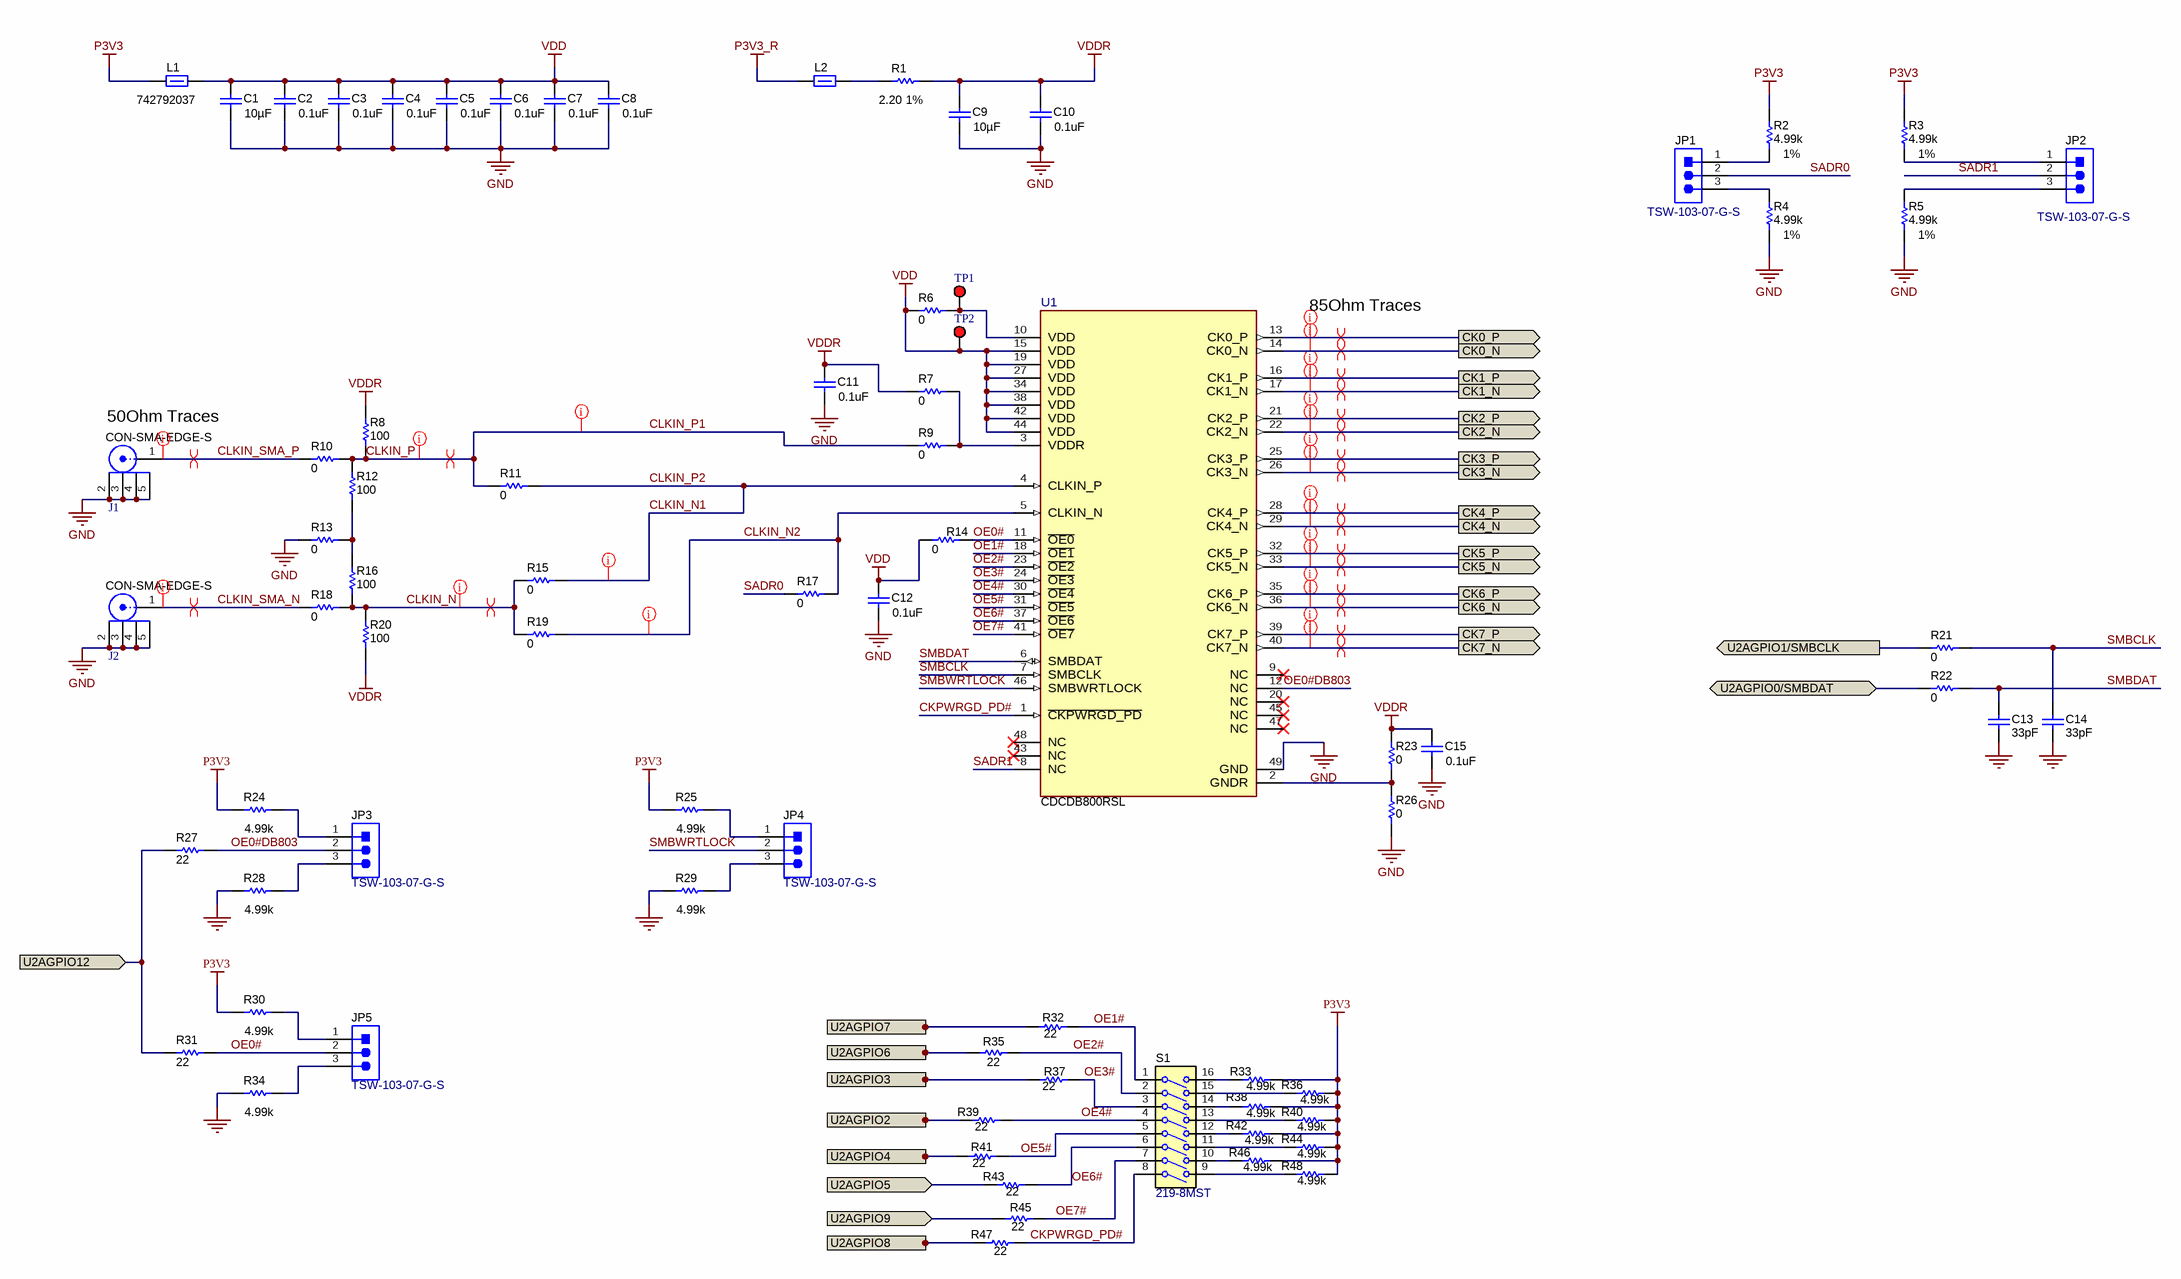
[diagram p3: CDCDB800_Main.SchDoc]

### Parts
C1  ValueDisplayed: 10µF  [0603]  (hidden comment: GRM188C81C106MA73D)
C2  ValueDisplayed: 0.1uF  [0402]  (hidden comment: GRM155R71A104KA01D)
C3  ValueDisplayed: 0.1uF  [0402]  (hidden comment: GRM155R71A104KA01D)
C4  ValueDisplayed: 0.1uF  [0402]  (hidden comment: GRM155R71A104KA01D)
C5  ValueDisplayed: 0.1uF  [0402]  (hidden comment: GRM155R71A104KA01D)
C6  ValueDisplayed: 0.1uF  [0402]  (hidden comment: GRM155R71A104KA01D)
C7  ValueDisplayed: 0.1uF  [0402]  (hidden comment: GRM155R71A104KA01D)
C8  ValueDisplayed: 0.1uF  [0402]  (hidden comment: GRM155R71A104KA01D)
C9  ValueDisplayed: 10µF  [0603]  (hidden comment: GRM188C81C106MA73D)
C10  ValueDisplayed: 0.1uF  [0402]  (hidden comment: GRM155R71A104KA01D)
C11  ValueDisplayed: 0.1uF  [0402]  (hidden comment: GRM155R71A104KA01D)
C12  ValueDisplayed: 0.1uF  [0402]  (hidden comment: GRM155R71A104KA01D)
C13  ValueDisplayed: 33pF  [0603S]  (hidden comment: 06031A330JAT2A)
C14  ValueDisplayed: 33pF  [0603S]  (hidden comment: 06031A330JAT2A)
C15  ValueDisplayed: 0.1uF  [0402]  (hidden comment: GRM155R71A104KA01D)
J1  CON-SMA-EDGE-S  [FP-SMA-EDGE-S-CUSTOM]
J2  CON-SMA-EDGE-S  [FP-SMA-EDGE-S-CUSTOM]
JP1  TSW-103-07-G-S  [TSW-103-07-G-S]
JP2  TSW-103-07-G-S  [TSW-103-07-G-S]
JP3  TSW-103-07-G-S  [TSW-103-07-G-S]
JP4  TSW-103-07-G-S  [TSW-103-07-G-S]
JP5  TSW-103-07-G-S  [TSW-103-07-G-S]
L1  742792037  [0805_HV]
L2  742792037  [0805_HV]  (value not drawn)
R1  Tolerance_%: 1%  ValueDisplayed: 2.20  [0603]  (hidden comment: ERJ-3RQF2R2V)
R2  Value1: 1%  ValueDisplayed: 4.99k  [0402]  (hidden comment: RC0402FR-074K99L)
R3  Value1: 1%  ValueDisplayed: 4.99k  [0402]  (hidden comment: RC0402FR-074K99L)
R4  Value1: 1%  ValueDisplayed: 4.99k  [0402]  (hidden comment: RC0402FR-074K99L)
R5  Value1: 1%  ValueDisplayed: 4.99k  [0402]  (hidden comment: RC0402FR-074K99L)
R6  ValueDisplayed: 0  [0603]  (hidden comment: MCT06030Z0000ZP500)
R7  ValueDisplayed: 0  [0603]  (hidden comment: RC0603JR-070RL)
R8  ValueDisplayed: 100  [0603]  (hidden comment: CRCW0603100RFKEA)
R9  ValueDisplayed: 0  [0603]  (hidden comment: RC0603JR-070RL)
R10  ValueDisplayed: 0  [0603]  (hidden comment: RC0603JR-070RL)
R11  ValueDisplayed: 0  [0603]  (hidden comment: RC0603JR-070RL)
R12  ValueDisplayed: 100  [0603]  (hidden comment: CRCW0603100RFKEA)
R13  ValueDisplayed: 0  [0603]  (hidden comment: RC0603JR-070RL)
R14  ValueDisplayed: 0  [0603]  (hidden comment: MCT06030Z0000ZP500)
R15  ValueDisplayed: 0  [0603]  (hidden comment: RC0603JR-070RL)
R16  ValueDisplayed: 100  [0603]  (hidden comment: CRCW0603100RFKEA)
R17  ValueDisplayed: 0  [0603]  (hidden comment: RC0603JR-070RL)
R18  ValueDisplayed: 0  [0603]  (hidden comment: RC0603JR-070RL)
R19  ValueDisplayed: 0  [0603]  (hidden comment: RC0603JR-070RL)
R20  ValueDisplayed: 100  [0603]  (hidden comment: CRCW0603100RFKEA)
R21  ValueDisplayed: 0  [0603L]  (hidden comment: CRCW06030000Z0EA)
R22  ValueDisplayed: 0  [0603L]  (hidden comment: CRCW06030000Z0EA)
R23  ValueDisplayed: 0  [0603]  (hidden comment: MCT06030Z0000ZP500)
R24  ValueDisplayed: 4.99k  [0402]  (hidden comment: RC0402FR-074K99L)
R25  ValueDisplayed: 4.99k  [0402]  (hidden comment: RC0402FR-074K99L)
R26  ValueDisplayed: 0  [0603]  (hidden comment: MCT06030Z0000ZP500)
R27  ValueDisplayed: 22  [0603]  (hidden comment: CRCW060322R0JNEA)
R28  ValueDisplayed: 4.99k  [0402]  (hidden comment: RC0402FR-074K99L)
R29  ValueDisplayed: 4.99k  [0402]  (hidden comment: RC0402FR-074K99L)
R30  ValueDisplayed: 4.99k  [0402]  (hidden comment: RC0402FR-074K99L)
R31  ValueDisplayed: 22  [0603]  (hidden comment: CRCW060322R0JNEA)
R32  ValueDisplayed: 22  [0603]  (hidden comment: CRCW060322R0JNEA)
R33  ValueDisplayed: 4.99k  [0402]  (hidden comment: RC0402FR-074K99L)
R34  ValueDisplayed: 4.99k  [0402]  (hidden comment: RC0402FR-074K99L)
R35  ValueDisplayed: 22  [0603]  (hidden comment: CRCW060322R0JNEA)
R36  ValueDisplayed: 4.99k  [0402]  (hidden comment: RC0402FR-074K99L)
R37  ValueDisplayed: 22  [0603]  (hidden comment: CRCW060322R0JNEA)
R38  ValueDisplayed: 4.99k  [0402]  (hidden comment: RC0402FR-074K99L)
R39  ValueDisplayed: 22  [0603]  (hidden comment: CRCW060322R0JNEA)
R40  ValueDisplayed: 4.99k  [0402]  (hidden comment: RC0402FR-074K99L)
R41  ValueDisplayed: 22  [0603]  (hidden comment: CRCW060322R0JNEA)
R42  ValueDisplayed: 4.99k  [0402]  (hidden comment: RC0402FR-074K99L)
R43  ValueDisplayed: 22  [0603]  (hidden comment: CRCW060322R0JNEA)
R44  ValueDisplayed: 4.99k  [0402]  (hidden comment: RC0402FR-074K99L)
R45  ValueDisplayed: 22  [0603]  (hidden comment: CRCW060322R0JNEA)
R46  ValueDisplayed: 4.99k  [0402]  (hidden comment: RC0402FR-074K99L)
R47  ValueDisplayed: 22  [0603]  (hidden comment: CRCW060322R0JNEA)
R48  ValueDisplayed: 4.99k  [0402]  (hidden comment: RC0402FR-074K99L)
S1  219-8MST  [SW_219-8MST]
TP1  5010  [Keystone5010]  (value not drawn)
TP2  5010  [Keystone5010]  (value not drawn)
U1  CDCDB800RSL  [RSL0048B-MFG]

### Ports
CK0_N (out), CK0_P (out), CK1_N (out), CK1_P (out), CK2_N (out), CK2_P (out), CK3_N (out), CK3_P (out), CK4_N (out), CK4_P (out), CK5_N (out), CK5_P (out), CK6_N (out), CK6_P (out), CK7_N (out), CK7_P (out), U2AGPIO0/SMBDAT (bidir), U2AGPIO1/SMBCLK (out), U2AGPIO2 (in), U2AGPIO3 (in), U2AGPIO4 (in), U2AGPIO5 (in), U2AGPIO6 (in), U2AGPIO7 (in), U2AGPIO8 (in), U2AGPIO9 (in), U2AGPIO12 (in)

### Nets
GND: C1.2 C2.2 C3.2 C4.2 C5.2 C6.2 C7.2 C8.2 C9.2 C10.2 C11.2 C12.2 C13.2 C14.2 C15.2 J1.2 J1.3 J1.4 J1.5 J2.2 J2.3 J2.4 J2.5 R4.1 R5.1 R13.1 R26.1 R28.2 R29.2 R34.2 U1.49(GND)
P3V3: L1.1 R2.2 R3.2 R24.2 R25.2 R30.2 R33.1 R36.1 R38.1 R40.1 R42.1 R44.2 R46.2 R48.2
P3V3_R: L2.1
VDD: C1.1 C2.1 C3.1 C4.1 C5.1 C6.1 C7.1 C8.1 C12.1 L1.2 R6.1 R14.2 TP2.1 U1.15(VDD) U1.19(VDD) U1.27(VDD) U1.34(VDD) U1.38(VDD) U1.42(VDD) U1.44(VDD)
VDDR: C9.1 C10.1 C11.1 C15.1 R1.2 R7.1 R8.1 R20.2 R23.2
CK0_N: U1.14(CK0_N) ; port CK0_N
CK0_P: U1.13(CK0_P) ; port CK0_P
CK1_N: U1.17(CK1_N) ; port CK1_N
CK1_P: U1.16(CK1_P) ; port CK1_P
CK2_N: U1.22(CK2_N) ; port CK2_N
CK2_P: U1.21(CK2_P) ; port CK2_P
CK3_N: U1.26(CK3_N) ; port CK3_N
CK3_P: U1.25(CK3_P) ; port CK3_P
CK4_N: U1.29(CK4_N) ; port CK4_N
CK4_P: U1.28(CK4_P) ; port CK4_P
CK5_N: U1.33(CK5_N) ; port CK5_N
CK5_P: U1.32(CK5_P) ; port CK5_P
CK6_N: U1.36(CK6_N) ; port CK6_N
CK6_P: U1.35(CK6_P) ; port CK6_P
CK7_N: U1.40(CK7_N) ; port CK7_N
CK7_P: U1.39(CK7_P) ; port CK7_P
CKPWRGD_PD#: R47.2 S1.8 U1.1(~{CKPWRGD_PD})
CLKIN_N: R15.1 R16.2 R18.2 R19.1 R20.1
CLKIN_N1: R11.2 R15.2 U1.4(CLKIN_P)  [also labelled CLKIN_P2]
CLKIN_N2: R17.2 R19.2 U1.5(CLKIN_N)
CLKIN_P: R8.2 R9.1 R10.2 R11.1 R12.1  [also labelled CLKIN_P1]
CLKIN_SMA_N: J2.1 R18.1
CLKIN_SMA_P: J1.1 R10.1
GPIO2: R39.1 ; port U2AGPIO2
GPIO3: R37.1 ; port U2AGPIO3
GPIO4: R41.1 ; port U2AGPIO4
GPIO5: R43.1 ; port U2AGPIO5
GPIO6: R35.1 ; port U2AGPIO6
GPIO7: R32.1 ; port U2AGPIO7
GPIO8: R47.1 ; port U2AGPIO8
GPIO9: R45.1 ; port U2AGPIO9
GPIO12: R27.1 R31.1 ; port U2AGPIO12
OE0#: JP5.2 R14.1 R31.2 U1.11(~{OE0})
OE0#DB803: JP3.2 R27.2 U1.12(NC)
OE1#: R32.2 S1.1 U1.18(~{OE1})
OE2#: R35.2 S1.2 U1.23(~{OE2})
OE3#: R37.2 S1.3 U1.24(~{OE3})
OE4#: R39.2 S1.4 U1.30(~{OE4})
OE5#: R41.2 S1.5 U1.31(~{OE5})
OE6#: R43.2 S1.6 U1.37(~{OE6})
OE7#: R45.2 S1.7 U1.41(~{OE7})
SADR0: JP1.2 R17.1
SADR1: JP2.2 U1.8(NC)
SCL: R21.1 ; port U2AGPIO1/SMBCLK
SDA: R22.1 ; port U2AGPIO0/SMBDAT
SMBCLK: C14.1 R21.2 U1.7(SMBCLK)
SMBDAT: C13.1 R22.2 U1.6(SMBDAT)
SMBWRTLOCK: JP4.2 U1.46(SMBWRTLOCK)
NetJP1_1: JP1.1 R2.1
NetJP1_3: JP1.3 R4.2
NetJP2_1: JP2.1 R3.1
NetJP2_3: JP2.3 R5.2
NetJP3_1: JP3.1 R24.1
NetJP3_3: JP3.3 R28.1
NetJP4_1: JP4.1 R25.1
NetJP4_3: JP4.3 R29.1
NetJP5_1: JP5.1 R30.1
NetJP5_3: JP5.3 R34.1
NetL2_2: L2.2 R1.1
NetR6_2: R6.2 TP1.1 U1.10(VDD)
NetR7_2: R7.2 R9.2 U1.3(VDDR)
NetR12_2: R12.2 R13.2 R16.1
NetR23_1: R23.1 R26.2 U1.2(GNDR)
NetR33_2: R33.2 S1.16(1A)
NetR36_2: R36.2 S1.15(2A)
NetR38_2: R38.2 S1.14(3A)
NetR40_2: R40.2 S1.13(4A)
NetR42_2: R42.2 S1.12(5A)
NetR44_1: R44.1 S1.11(6A)
NetR46_1: R46.1 S1.10(7A)
NetR48_1: R48.1 S1.9(8A)

Not connected (* = marked no-connect by the designer): U1 9(NC)* 20(NC)* 43(NC)* 45(NC)* 47(NC)* 48(NC)*

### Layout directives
differential pair: CK0_N, CK0_P, CK1_N, CK1_P, CK2_N, CK2_P, CK3_N, CK3_P, CK4_N, CK4_P, CK5_N, CK5_P, CK6_N, CK6_P, CK7_N, CK7_P, CLKIN_N, CLKIN_P, CLKIN_SMA_N, CLKIN_SMA_P
net class 85ohms: CK0_N, CK0_P, CK1_N, CK1_P, CK2_N, CK2_P, CK3_N, CK3_P, CK4_N, CK4_P, CK5_N, CK5_P, CK6_N, CK6_P, CK7_N, CK7_P
net class 50ohms: CLKIN_N, CLKIN_N1, CLKIN_N2, CLKIN_P, CLKIN_SMA_N, CLKIN_SMA_P

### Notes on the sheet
- (near U1) 85Ohm Traces
- (near J1) 50Ohm Traces

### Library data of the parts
C1 C9 = CMP-0086062-1: CAP, CERM, 10 µF, 16 V,+/- 20%, X6S, 0603; Manufacturer: MuRata; U/M: EA; AEC Category: Q200; VDC_V: 16V; SizeX_mm: 1.6; SizeY_mm: 0.8; SizeZ_mm: 1; Value: 10uF; SizeArea_mm2: 1.28; TaMin_C: -55°C; Polarized: N; SizeAreaWB_mm2: 4.68; TaMax_C: 105°C
C2-C8 C10-C12 C15 = CMP-0006629-2: CAP, CERM, 0.1 uF, 10 V, +/- 10%, X7R, 0402; Manufacturer: MuRata; TaMin_C: -55°C; Polarized: N; SizeAreaWB_mm2: 3; Value1: Unknown; U/M: EA; Value: 0.1uF; TaMax_C: 125°C; SizeZ_mm: 0.6; SizeX_mm: 1; SizeY_mm: 0.5; Value2: 10V; Cap_F: 100nF; AEC Category: Q200
C13 C14 = CMP-0006722-4: CAP, CERM, 33 pF, 100 V, +/- 5%, C0G/NP0, 0603; Manufacturer: AVX; Polarized: N; Value: 33pF; U/M: EA; ESR_ohm: 0.209; Value1: 0.209 ohm; VDC_V: 100V; TaMin_C: -55°C; TaMax_C: 125°C; Cap_Case: 0603; AEC Category: Q200; SizeArea_mm2: 1.28; SizeAreaWB_mm2: 4.68; SizeX_mm: 1.6; SizeY_mm: 0.8; SizeZ_mm: 1
J1 J2 = CMP-0088000-4: CONN SMA JACK STR EDGE MNT; Manufacturer: RF Solutions Ltd.; ContactFinish: Gold; Shrouded: true
JP1-JP5 = CMP-0075407-2: Header, 100mil, 3x1, Gold, TH; Manufacturer: Samtec; Cert_CSA: Y; Cert_CULUS: N; Current_A: 6.3A; Gender: Male; Green_Lifecycle: Active; Green_REACh: Passed; Pitch_mm: 2.54; Row_Count: 1; Voltage_V: 550V
L1 L2 = CMP-0003081-1: Ferrite Bead, 330 ohm @ 100 MHz, 2 A, 0805; Manufacturer: Wurth Elektronik; Ztyp@1GHz_Ohm: 170.834; ZTyp@100MHz_Ohm: 330; SizeAreaWB_mm2: 6.75; DCR_ohm: 0.08; Value1: 0.08 ohm; Value: 330 ohm; Imax_A: 2A; SizeZ_mm: 1.45; SizeX_mm: 2; SizeY_mm: 1.25; SizeArea_mm2: 2.5
R1 = CMP-0022711-2: RES, 2.20, 1%, 0.1 W, 0603; Manufacturer: Panasonic; Power_W: 100mW; TempCo: 200 ppm/C; Value_Code: 2R20; U/M: EA; Value: 2.20; Res_ohm: 2.2; SizeX_mm: 1.6; SizeY_mm: 0.8; SizeZ_mm: 1; Value2: 0.1W; SizeArea_mm2: 1.28; AEC Category: Q200
R2-R5 R24 R25 R28-R30 R33 R34 R36 R38 R40 R42 R44 R46 R48 = CMP-0026740-1: RES, 4.99 k, 1%, 0.063 W, 0402; Manufacturer: Yageo America; Power_W: 63mW; TempCo: 100 ppm/C; Value_Code: 4k99; U/M: EA; Value: 4.99k; EIA_Code: E96; SizeX_mm: 1; SizeY_mm: 0.5; SizeZ_mm: 0.6; Value2: 0.063W; AEC Qualified: N; VDC_V: 50V; AEC Category: Q200
R6 R14 R23 R26 = CMP-0025884-3: RES, 0, 5%, 0.125 W, 0603; Manufacturer: Vishay/Beyschlag; Power_W: 125mW; TempCo: ppm/C; Value_Code: 0000; U/M: EA; Value: 0; EIA_Code: E24; SizeX_mm: 1.6; SizeY_mm: 0.8; SizeZ_mm: 1; Value2: 0.125W; SizeArea_mm2: 1.28; AEC Qualified: N; AEC Category: Q200
R7 R9-R11 R13 R15 R17-R19 = CMP-0025885-5: RES, 0, 5%, 0.1 W, 0603; Manufacturer: Yageo; Power_W: 100mW; TempCo: 200 ppm/C; Value_Code: 0000; Value: 0; EIA_Code: E24; SizeX_mm: 1.6; SizeZ_mm: 1; Value2: 0.1W; SizeArea_mm2: 1.28; AEC Qualified: N; VDC_V: 75V; AEC Category: Q200; SizeY_mm: 0.8; SizeAreaWB_mm2: 4.68
R8 R12 R16 R20 = CMP-0021991-4: RES, 100, 1%, 0.1 W, AEC-Q200 Grade 0, 0603; Manufacturer: Vishay-Dale; Power_W: 100mW; TempCo: 100 ppm/C; Value_Code: 100R; Value: 100; EIA_Code: E96; SizeX_mm: 1.6; SizeY_mm: 0.8; SizeZ_mm: 1; Value2: 0.1W; SizeArea_mm2: 1.28; AEC Qualified: Y; VDC_V: 75V; AEC Category: Q200; AEC Grade: 0
R21 R22 = CMP-0025697-4: RES, 0, 5%, 0.1 W, AEC-Q200 Grade 0, 0603; Manufacturer: Vishay-Dale; Value: 0; Value_Code: 0000; Power_W: 100mW; Value2: 0.1W; VDC_V: 75V; TempCo: 200 ppm/C; EIA_Code: E24; AEC Category: Q200; AEC Qualified: Y; SizeArea_mm2: 1.28; SizeX_mm: 1.6; SizeY_mm: 0.8; SizeZ_mm: 1
R27 R31 R32 R35 R37 R39 R41 R43 R45 R47 = CMP-0025758-4: RES, 22, 5%, 0.1 W, AEC-Q200 Grade 0, 0603; Manufacturer: Vishay-Dale; Power_W: 100mW; TempCo: 200 ppm/C; Value_Code: 22R0; Value: 22; EIA_Code: E24; SizeX_mm: 1.6; SizeY_mm: 0.8; SizeZ_mm: 1; Value2: 0.1W; SizeArea_mm2: 1.28; AEC Qualified: Y; VDC_V: 75V; AEC Category: Q200; AEC Grade: 0
S1 = CMP-0002131-3: Switch, Slide, SPST 8 poles, SMT; Manufacturer: CTS Electrocomponents; VDC_V: 20V; SwitchFunction: Off-On; PositionCount: 8; CurrentRating_mA: 100A
TP1 TP2 = CMP-0055147-1: Test Point, Multipurpose, Red, TH; Manufacturer: Keystone; CNHeader: FALSE; Green_Lifecycle: Active; Green_REACh: Passed; ContactFinish: Silver; CT: TRUE
U1 = CMP-0091223-1: 8-output LP-HCSL clock buffer capable of distributing the reference clocks for PCIe Gen 1-5, QPI, UPI, SAS, and SATA interfaces; Manufacturer: Texas Instruments; Standoff Height: 0mm; Number Of Elements: 1; SizeZ_mm: 1mm; Min Supply Voltage: 2.97V; Logic Function: Non-Inverting; AEC Qualified: No; Number Of Outputs: 8; Nominal Supply Current: 5-63mA; Max Supply Voltage: 3.63V

## Sheet CDCDB800_Output.SchDoc: Output
size C; Date: Not shown in title block; ApprovedBy: Not shown in title block; CheckedBy: Not shown in title block; Author: Not shown in title block; CompanyName: Not shown in title block; DrawnBy: Robert Pulatie; Engineer: Not shown in title block; Organization: Not shown in title block; Address1: Not shown in title block; Address2: Not shown in title block; Address3: Not shown in title block; Address4: Not shown in title block; DocumentNumber: 4; Revision: Use project parameter SCH_Rev; SheetNumber: 4; SheetTotal: 6; PageSetup: Record=PageOptions¦CenterHorizontal=True¦CenterVertical=True¦PrintScale=1.00¦XCorrection=1.00¦YCorrection=1.00¦PrintKind=0¦BorderSize=5000000¦LeftOffset=0¦BottomOffset=0¦Orientation=2¦PaperLength=1000¦PaperWidth=1000¦Scale=100¦PaperSource=15¦PrintQuality=600¦MediaType=1¦DitherType=10¦PaperKind=Letter¦PrintScaleMode=1
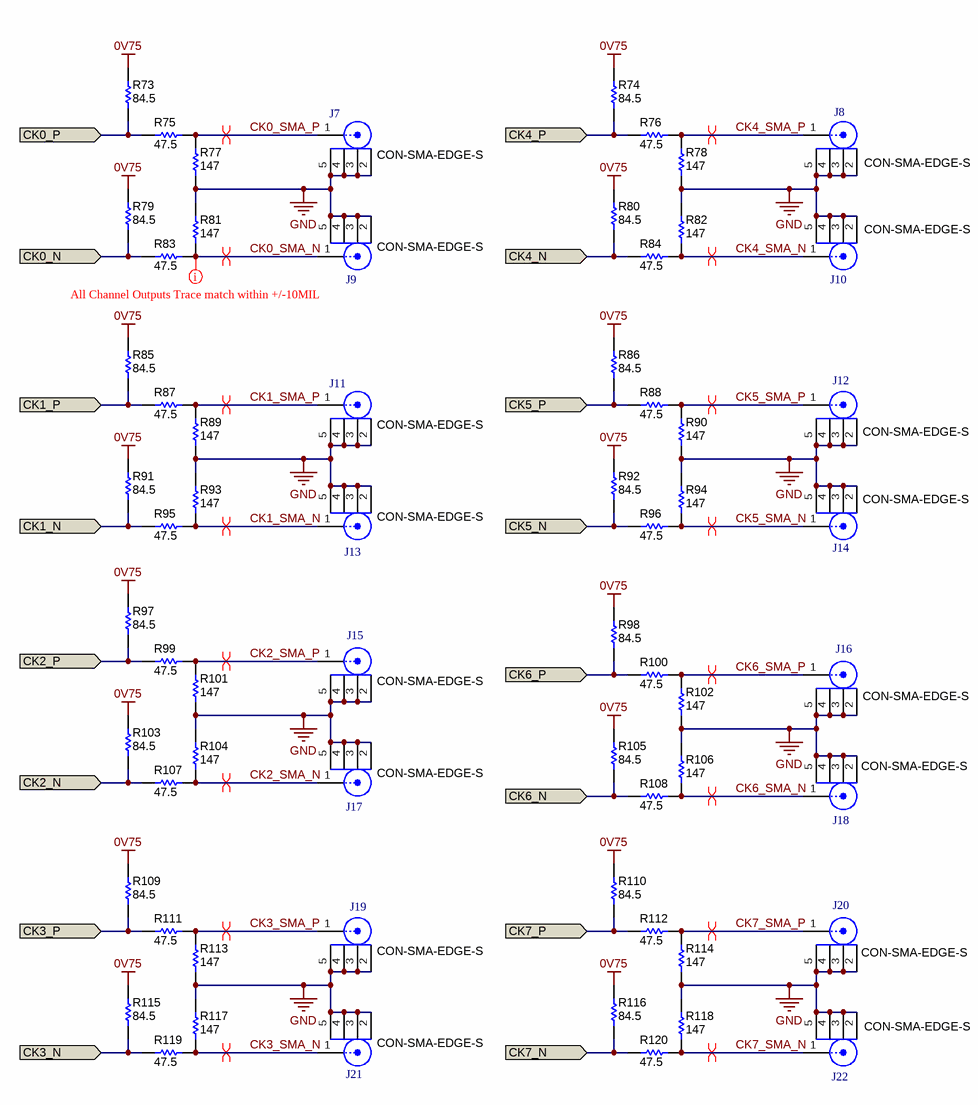
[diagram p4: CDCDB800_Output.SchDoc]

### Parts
J7  CON-SMA-EDGE-S  [FP-SMA-EDGE-S-CUSTOM]
J8  CON-SMA-EDGE-S  [FP-SMA-EDGE-S-CUSTOM]
J9  CON-SMA-EDGE-S  [FP-SMA-EDGE-S-CUSTOM]
J10  CON-SMA-EDGE-S  [FP-SMA-EDGE-S-CUSTOM]
J11  CON-SMA-EDGE-S  [FP-SMA-EDGE-S-CUSTOM]
J12  CON-SMA-EDGE-S  [FP-SMA-EDGE-S-CUSTOM]
J13  CON-SMA-EDGE-S  [FP-SMA-EDGE-S-CUSTOM]
J14  CON-SMA-EDGE-S  [FP-SMA-EDGE-S-CUSTOM]
J15  CON-SMA-EDGE-S  [FP-SMA-EDGE-S-CUSTOM]
J16  CON-SMA-EDGE-S  [FP-SMA-EDGE-S-CUSTOM]
J17  CON-SMA-EDGE-S  [FP-SMA-EDGE-S-CUSTOM]
J18  CON-SMA-EDGE-S  [FP-SMA-EDGE-S-CUSTOM]
J19  CON-SMA-EDGE-S  [FP-SMA-EDGE-S-CUSTOM]
J20  CON-SMA-EDGE-S  [FP-SMA-EDGE-S-CUSTOM]
J21  CON-SMA-EDGE-S  [FP-SMA-EDGE-S-CUSTOM]
J22  CON-SMA-EDGE-S  [FP-SMA-EDGE-S-CUSTOM]
R73  ValueDisplayed: 84.5  [0201]  (hidden comment: RC0201FR-0784R5L)
R74  ValueDisplayed: 84.5  [0201]  (hidden comment: RC0201FR-0784R5L)
R75  ValueDisplayed: 47.5  [0201]  (hidden comment: RC0201FR-0747R5L)
R76  ValueDisplayed: 47.5  [0201]  (hidden comment: RC0201FR-0747R5L)
R77  ValueDisplayed: 147  [0201]  (hidden comment: RC0201FR-07147RL)
R78  ValueDisplayed: 147  [0201]  (hidden comment: RC0201FR-07147RL)
R79  ValueDisplayed: 84.5  [0201]  (hidden comment: RC0201FR-0784R5L)
R80  ValueDisplayed: 84.5  [0201]  (hidden comment: RC0201FR-0784R5L)
R81  ValueDisplayed: 147  [0201]  (hidden comment: RC0201FR-07147RL)
R82  ValueDisplayed: 147  [0201]  (hidden comment: RC0201FR-07147RL)
R83  ValueDisplayed: 47.5  [0201]  (hidden comment: RC0201FR-0747R5L)
R84  ValueDisplayed: 47.5  [0201]  (hidden comment: RC0201FR-0747R5L)
R85  ValueDisplayed: 84.5  [0201]  (hidden comment: RC0201FR-0784R5L)
R86  ValueDisplayed: 84.5  [0201]  (hidden comment: RC0201FR-0784R5L)
R87  ValueDisplayed: 47.5  [0201]  (hidden comment: RC0201FR-0747R5L)
R88  ValueDisplayed: 47.5  [0201]  (hidden comment: RC0201FR-0747R5L)
R89  ValueDisplayed: 147  [0201]  (hidden comment: RC0201FR-07147RL)
R90  ValueDisplayed: 147  [0201]  (hidden comment: RC0201FR-07147RL)
R91  ValueDisplayed: 84.5  [0201]  (hidden comment: RC0201FR-0784R5L)
R92  ValueDisplayed: 84.5  [0201]  (hidden comment: RC0201FR-0784R5L)
R93  ValueDisplayed: 147  [0201]  (hidden comment: RC0201FR-07147RL)
R94  ValueDisplayed: 147  [0201]  (hidden comment: RC0201FR-07147RL)
R95  ValueDisplayed: 47.5  [0201]  (hidden comment: RC0201FR-0747R5L)
R96  ValueDisplayed: 47.5  [0201]  (hidden comment: RC0201FR-0747R5L)
R97  ValueDisplayed: 84.5  [0201]  (hidden comment: RC0201FR-0784R5L)
R98  ValueDisplayed: 84.5  [0201]  (hidden comment: RC0201FR-0784R5L)
R99  ValueDisplayed: 47.5  [0201]  (hidden comment: RC0201FR-0747R5L)
R100  ValueDisplayed: 47.5  [0201]  (hidden comment: RC0201FR-0747R5L)
R101  ValueDisplayed: 147  [0201]  (hidden comment: RC0201FR-07147RL)
R102  ValueDisplayed: 147  [0201]  (hidden comment: RC0201FR-07147RL)
R103  ValueDisplayed: 84.5  [0201]  (hidden comment: RC0201FR-0784R5L)
R104  ValueDisplayed: 147  [0201]  (hidden comment: RC0201FR-07147RL)
R105  ValueDisplayed: 84.5  [0201]  (hidden comment: RC0201FR-0784R5L)
R106  ValueDisplayed: 147  [0201]  (hidden comment: RC0201FR-07147RL)
R107  ValueDisplayed: 47.5  [0201]  (hidden comment: RC0201FR-0747R5L)
R108  ValueDisplayed: 47.5  [0201]  (hidden comment: RC0201FR-0747R5L)
R109  ValueDisplayed: 84.5  [0201]  (hidden comment: RC0201FR-0784R5L)
R110  ValueDisplayed: 84.5  [0201]  (hidden comment: RC0201FR-0784R5L)
R111  ValueDisplayed: 47.5  [0201]  (hidden comment: RC0201FR-0747R5L)
R112  ValueDisplayed: 47.5  [0201]  (hidden comment: RC0201FR-0747R5L)
R113  ValueDisplayed: 147  [0201]  (hidden comment: RC0201FR-07147RL)
R114  ValueDisplayed: 147  [0201]  (hidden comment: RC0201FR-07147RL)
R115  ValueDisplayed: 84.5  [0201]  (hidden comment: RC0201FR-0784R5L)
R116  ValueDisplayed: 84.5  [0201]  (hidden comment: RC0201FR-0784R5L)
R117  ValueDisplayed: 147  [0201]  (hidden comment: RC0201FR-07147RL)
R118  ValueDisplayed: 147  [0201]  (hidden comment: RC0201FR-07147RL)
R119  ValueDisplayed: 47.5  [0201]  (hidden comment: RC0201FR-0747R5L)
R120  ValueDisplayed: 47.5  [0201]  (hidden comment: RC0201FR-0747R5L)

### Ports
CK0_N (in), CK0_P (in), CK1_N (in), CK1_P (in), CK2_N (in), CK2_P (in), CK3_N (in), CK3_P (in), CK4_N (in), CK4_P (in), CK5_N (in), CK5_P (in), CK6_N (in), CK6_P (in), CK7_N (in), CK7_P (in)

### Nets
0V75: R73.2 R74.2 R79.2 R80.2 R85.2 R86.2 R91.2 R92.2 R97.2 R98.2 R103.2 R105.2 R109.2 R110.2 R115.2 R116.2
GND: J7.2 J7.3 J7.4 J7.5 J8.2 J8.3 J8.4 J8.5 J9.2 J9.3 J9.4 J9.5 J10.2 J10.3 J10.4 J10.5 J11.2 J11.3 J11.4 J11.5 J12.2 J12.3 J12.4 J12.5 J13.2 J13.3 J13.4 J13.5 J14.2 J14.3 J14.4 J14.5 J15.2 J15.3 J15.4 J15.5 J16.2 J16.3 J16.4 J16.5 J17.2 J17.3 J17.4 J17.5 J18.2 J18.3 J18.4 J18.5 J19.2 J19.3 J19.4 J19.5 J20.2 J20.3 J20.4 J20.5 J21.2 J21.3 J21.4 J21.5 J22.2 J22.3 J22.4 J22.5 R77.1 R78.1 R81.2 R82.2 R89.1 R90.1 R93.2 R94.2 R101.1 R102.1 R104.2 R106.2 R113.1 R114.1 R117.2 R118.2
CK0_N: R79.1 R83.1 ; port CK0_N
CK0_P: R73.1 R75.1 ; port CK0_P
CK0_SMA_N: J9.1 R81.1 R83.2
CK0_SMA_P: J7.1 R75.2 R77.2
CK1_N: R91.1 R95.1 ; port CK1_N
CK1_P: R85.1 R87.1 ; port CK1_P
CK1_SMA_N: J13.1 R93.1 R95.2
CK1_SMA_P: J11.1 R87.2 R89.2
CK2_N: R103.1 R107.1 ; port CK2_N
CK2_P: R97.1 R99.1 ; port CK2_P
CK2_SMA_N: J17.1 R104.1 R107.2
CK2_SMA_P: J15.1 R99.2 R101.2
CK3_N: R115.1 R119.1 ; port CK3_N
CK3_P: R109.1 R111.1 ; port CK3_P
CK3_SMA_N: J21.1 R117.1 R119.2
CK3_SMA_P: J19.1 R111.2 R113.2
CK4_N: R80.1 R84.1 ; port CK4_N
CK4_P: R74.1 R76.1 ; port CK4_P
CK4_SMA_N: J10.1 R82.1 R84.2
CK4_SMA_P: J8.1 R76.2 R78.2
CK5_N: R92.1 R96.1 ; port CK5_N
CK5_P: R86.1 R88.1 ; port CK5_P
CK5_SMA_N: J14.1 R94.1 R96.2
CK5_SMA_P: J12.1 R88.2 R90.2
CK6_N: R105.1 R108.1 ; port CK6_N
CK6_P: R98.1 R100.1 ; port CK6_P
CK6_SMA_N: J18.1 R106.1 R108.2
CK6_SMA_P: J16.1 R100.2 R102.2
CK7_N: R116.1 R120.1 ; port CK7_N
CK7_P: R110.1 R112.1 ; port CK7_P
CK7_SMA_N: J22.1 R118.1 R120.2
CK7_SMA_P: J20.1 R112.2 R114.2

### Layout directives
differential pair: CK0_SMA_N, CK0_SMA_P, CK1_SMA_N, CK1_SMA_P, CK2_SMA_N, CK2_SMA_P, CK3_SMA_N, CK3_SMA_P, CK4_SMA_N, CK4_SMA_P, CK5_SMA_N, CK5_SMA_P, CK6_SMA_N, CK6_SMA_P, CK7_SMA_N, CK7_SMA_P
mark named All Channel Outputs Trace match within +/-10MIL: CK0_SMA_N

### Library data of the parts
J7-J22 = CMP-0088000-4: as J1 on sheet CDCDB800_Main
R73 R79 R85 R86 R91 R92 R97 R98 R103 R105 R109 R110 R115 R116 = CMP-0027898-1: RES, 84.5, 1%, 0.05 W, 0201; Manufacturer: Yageo America; Power_W: 50mW; TempCo: 200 ppm/C; Value_Code: 84R5; U/M: EA; Value: 84.5; EIA_Code: E96; SizeX_mm: 0.6; SizeY_mm: 0.3; SizeZ_mm: 0.26; Value2: 0.05W; SizeArea_mm2: 0.18; AEC Qualified: N; VDC_V: 25V; AEC Category: Q200
R74 R80 = CMP-0027898-1: RES, 84.5, 1%, 0.05 W, 0201; Manufacturer: Yageo America; Power_W: 50mW; TempCo: 200 ppm/C; Value_Code: 84R5; Value: 84.5; EIA_Code: E96; SizeX_mm: 0.6; SizeY_mm: 0.3; SizeZ_mm: 0.26; Value2: 0.05W; SizeArea_mm2: 0.18; AEC Qualified: N; VDC_V: 25V; AEC Category: Q200; U/M: EA
R75 R76 R83 R84 R87 R88 R95 R96 R99 R100 R107 R108 R111 R112 R119 R120 = CMP-0027724-1: RES, 47.5, 1%, 0.05 W, 0201; Manufacturer: Yageo America; Power_W: 50mW; TempCo: 200 ppm/C; Value_Code: 47R5; U/M: EA; Value: 47.5; EIA_Code: E96; SizeX_mm: 0.6; SizeY_mm: 0.3; SizeZ_mm: 0.26; Value2: 0.05W; SizeArea_mm2: 0.18; AEC Qualified: N; VDC_V: 25V; AEC Category: Q200
R77 R78 R81 R82 R89 R90 R93 R94 R101 R102 R104 R106 R113 R114 R117 R118 = CMP-0027359-2: RES, 147, 1%, 0.05 W, 0201; Manufacturer: Yageo America; Power_W: 50mW; TempCo: 200 ppm/C; Value_Code: 147R; U/M: EA; Value: 147; EIA_Code: E96; SizeX_mm: 0.6; SizeY_mm: 0.3; SizeZ_mm: 0.26; Value2: 0.05W; SizeArea_mm2: 0.18; AEC Qualified: N; VDC_V: 25V; AEC Category: Q200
